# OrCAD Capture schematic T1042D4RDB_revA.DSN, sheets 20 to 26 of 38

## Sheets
20 20 EC2 PHY: size B
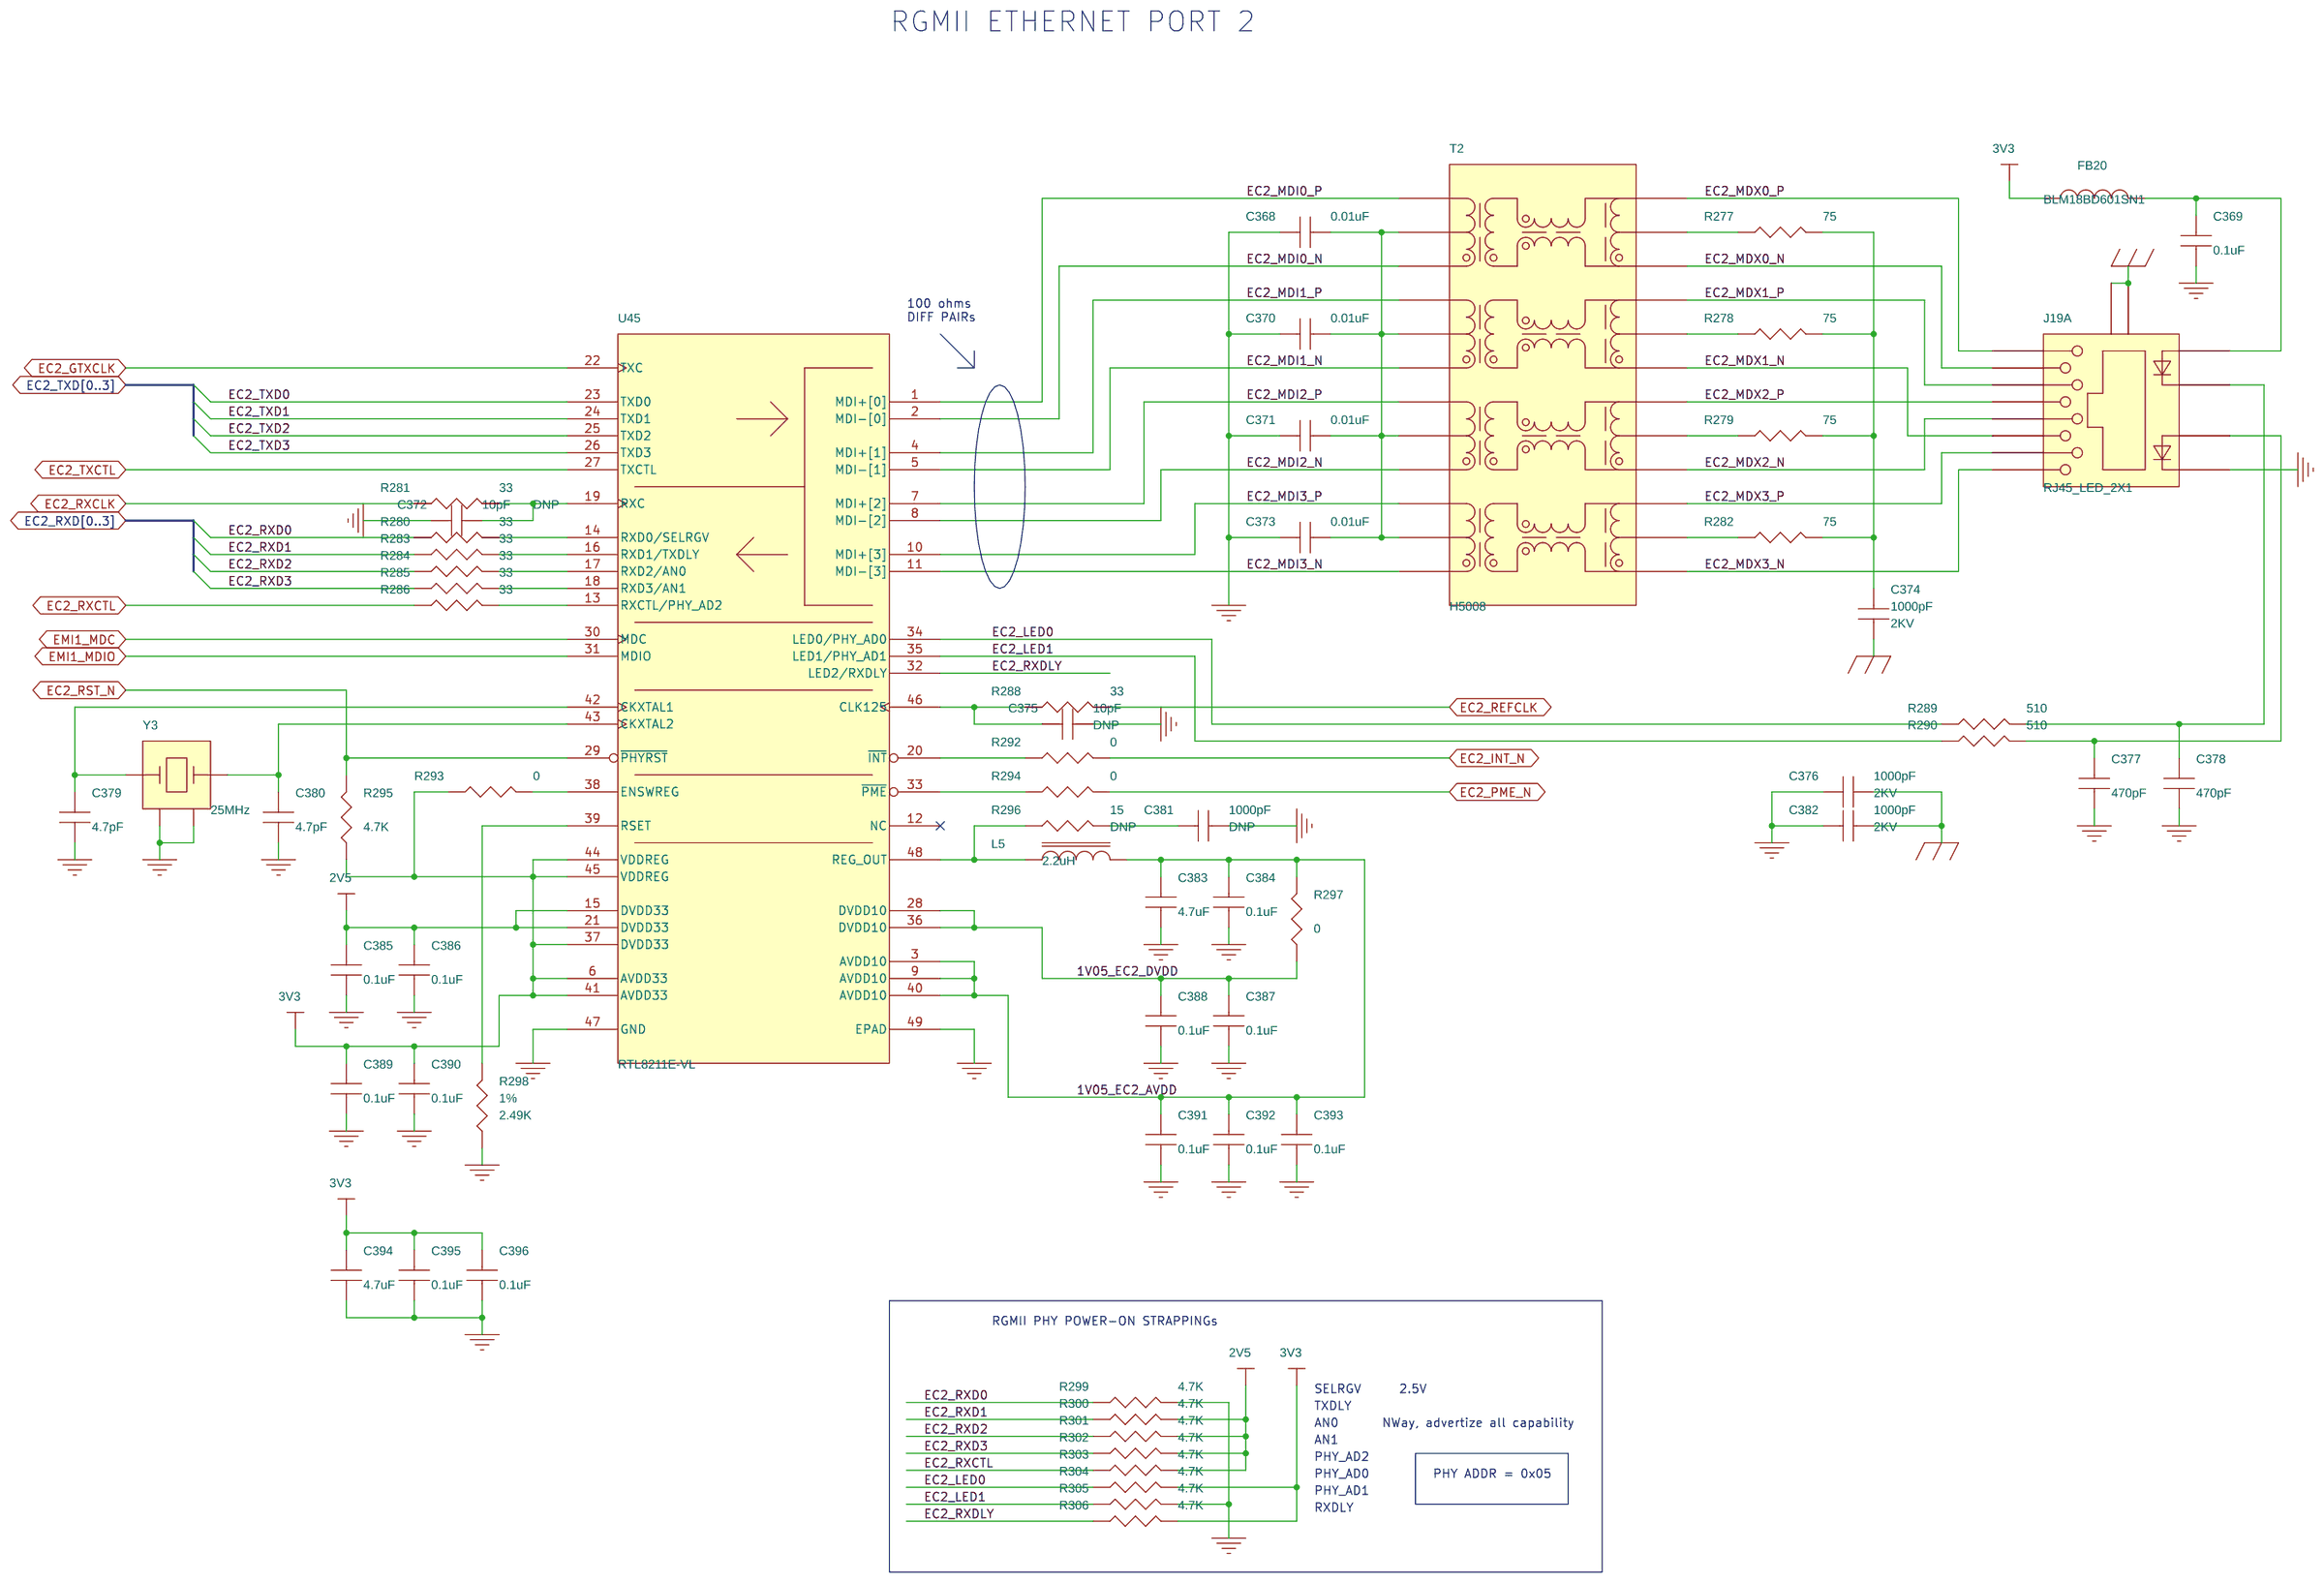
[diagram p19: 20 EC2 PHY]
21 21 SG PHY: size B
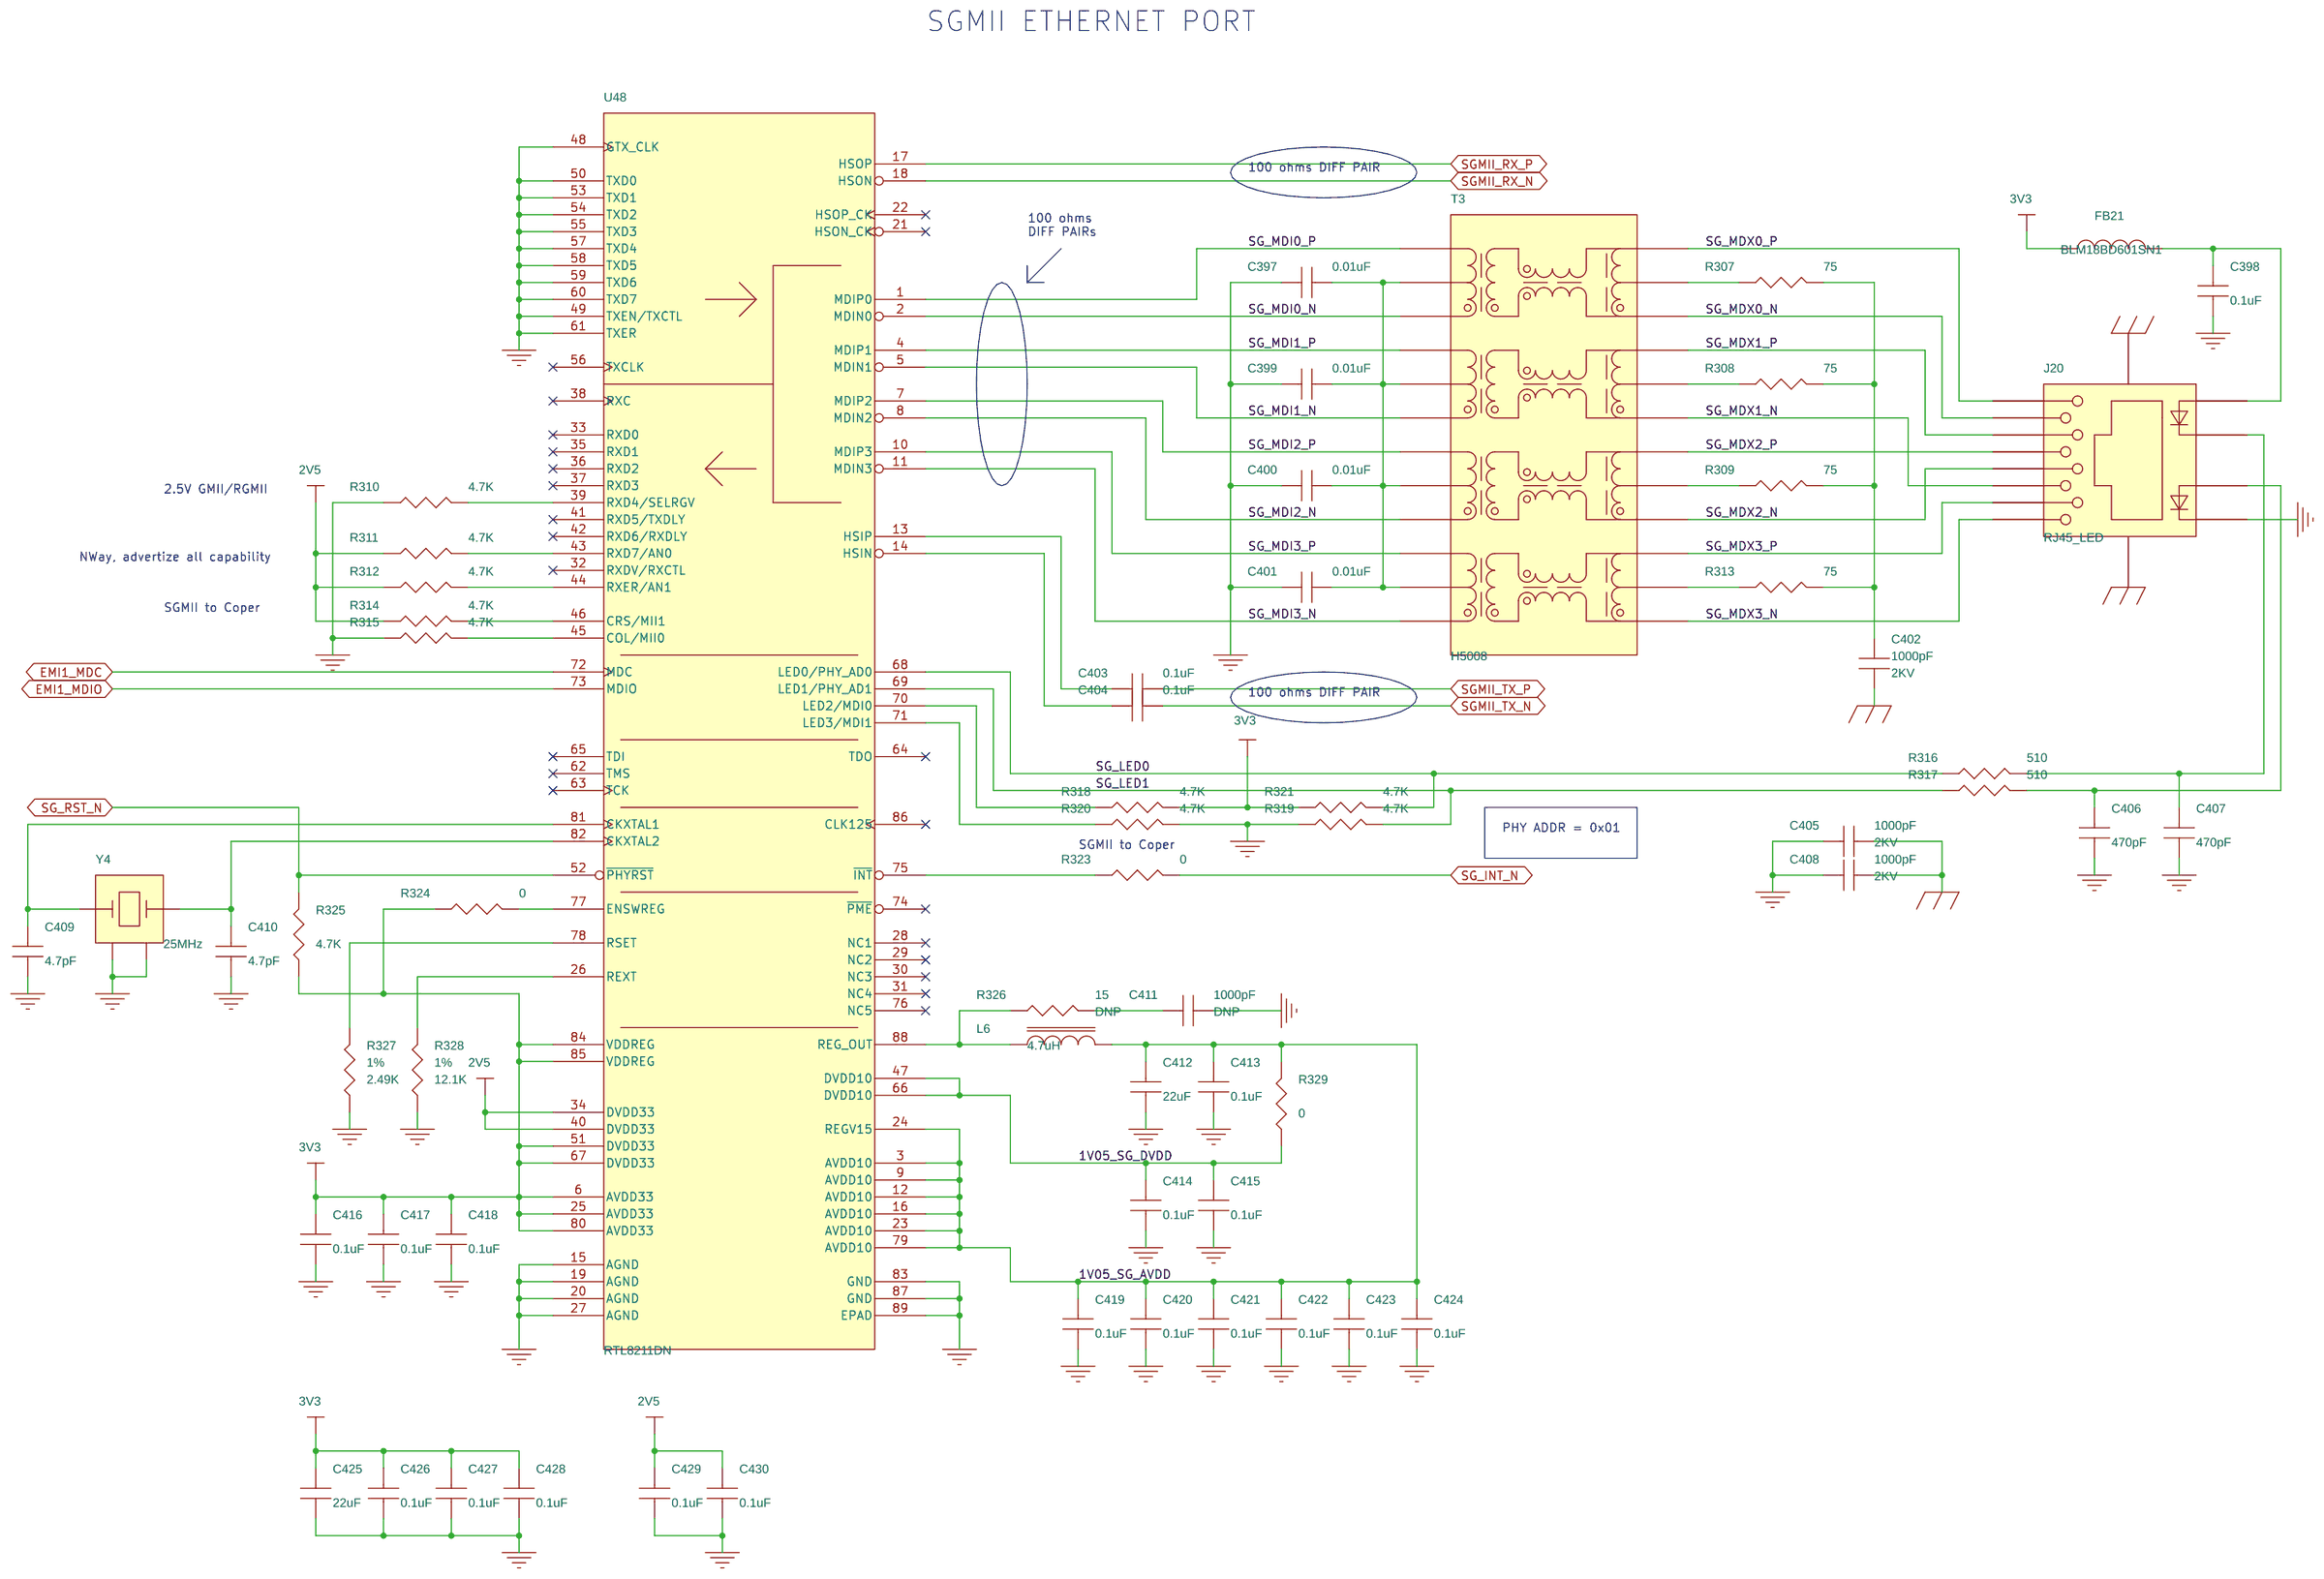
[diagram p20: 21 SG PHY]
22 22 SG PHY1: size B
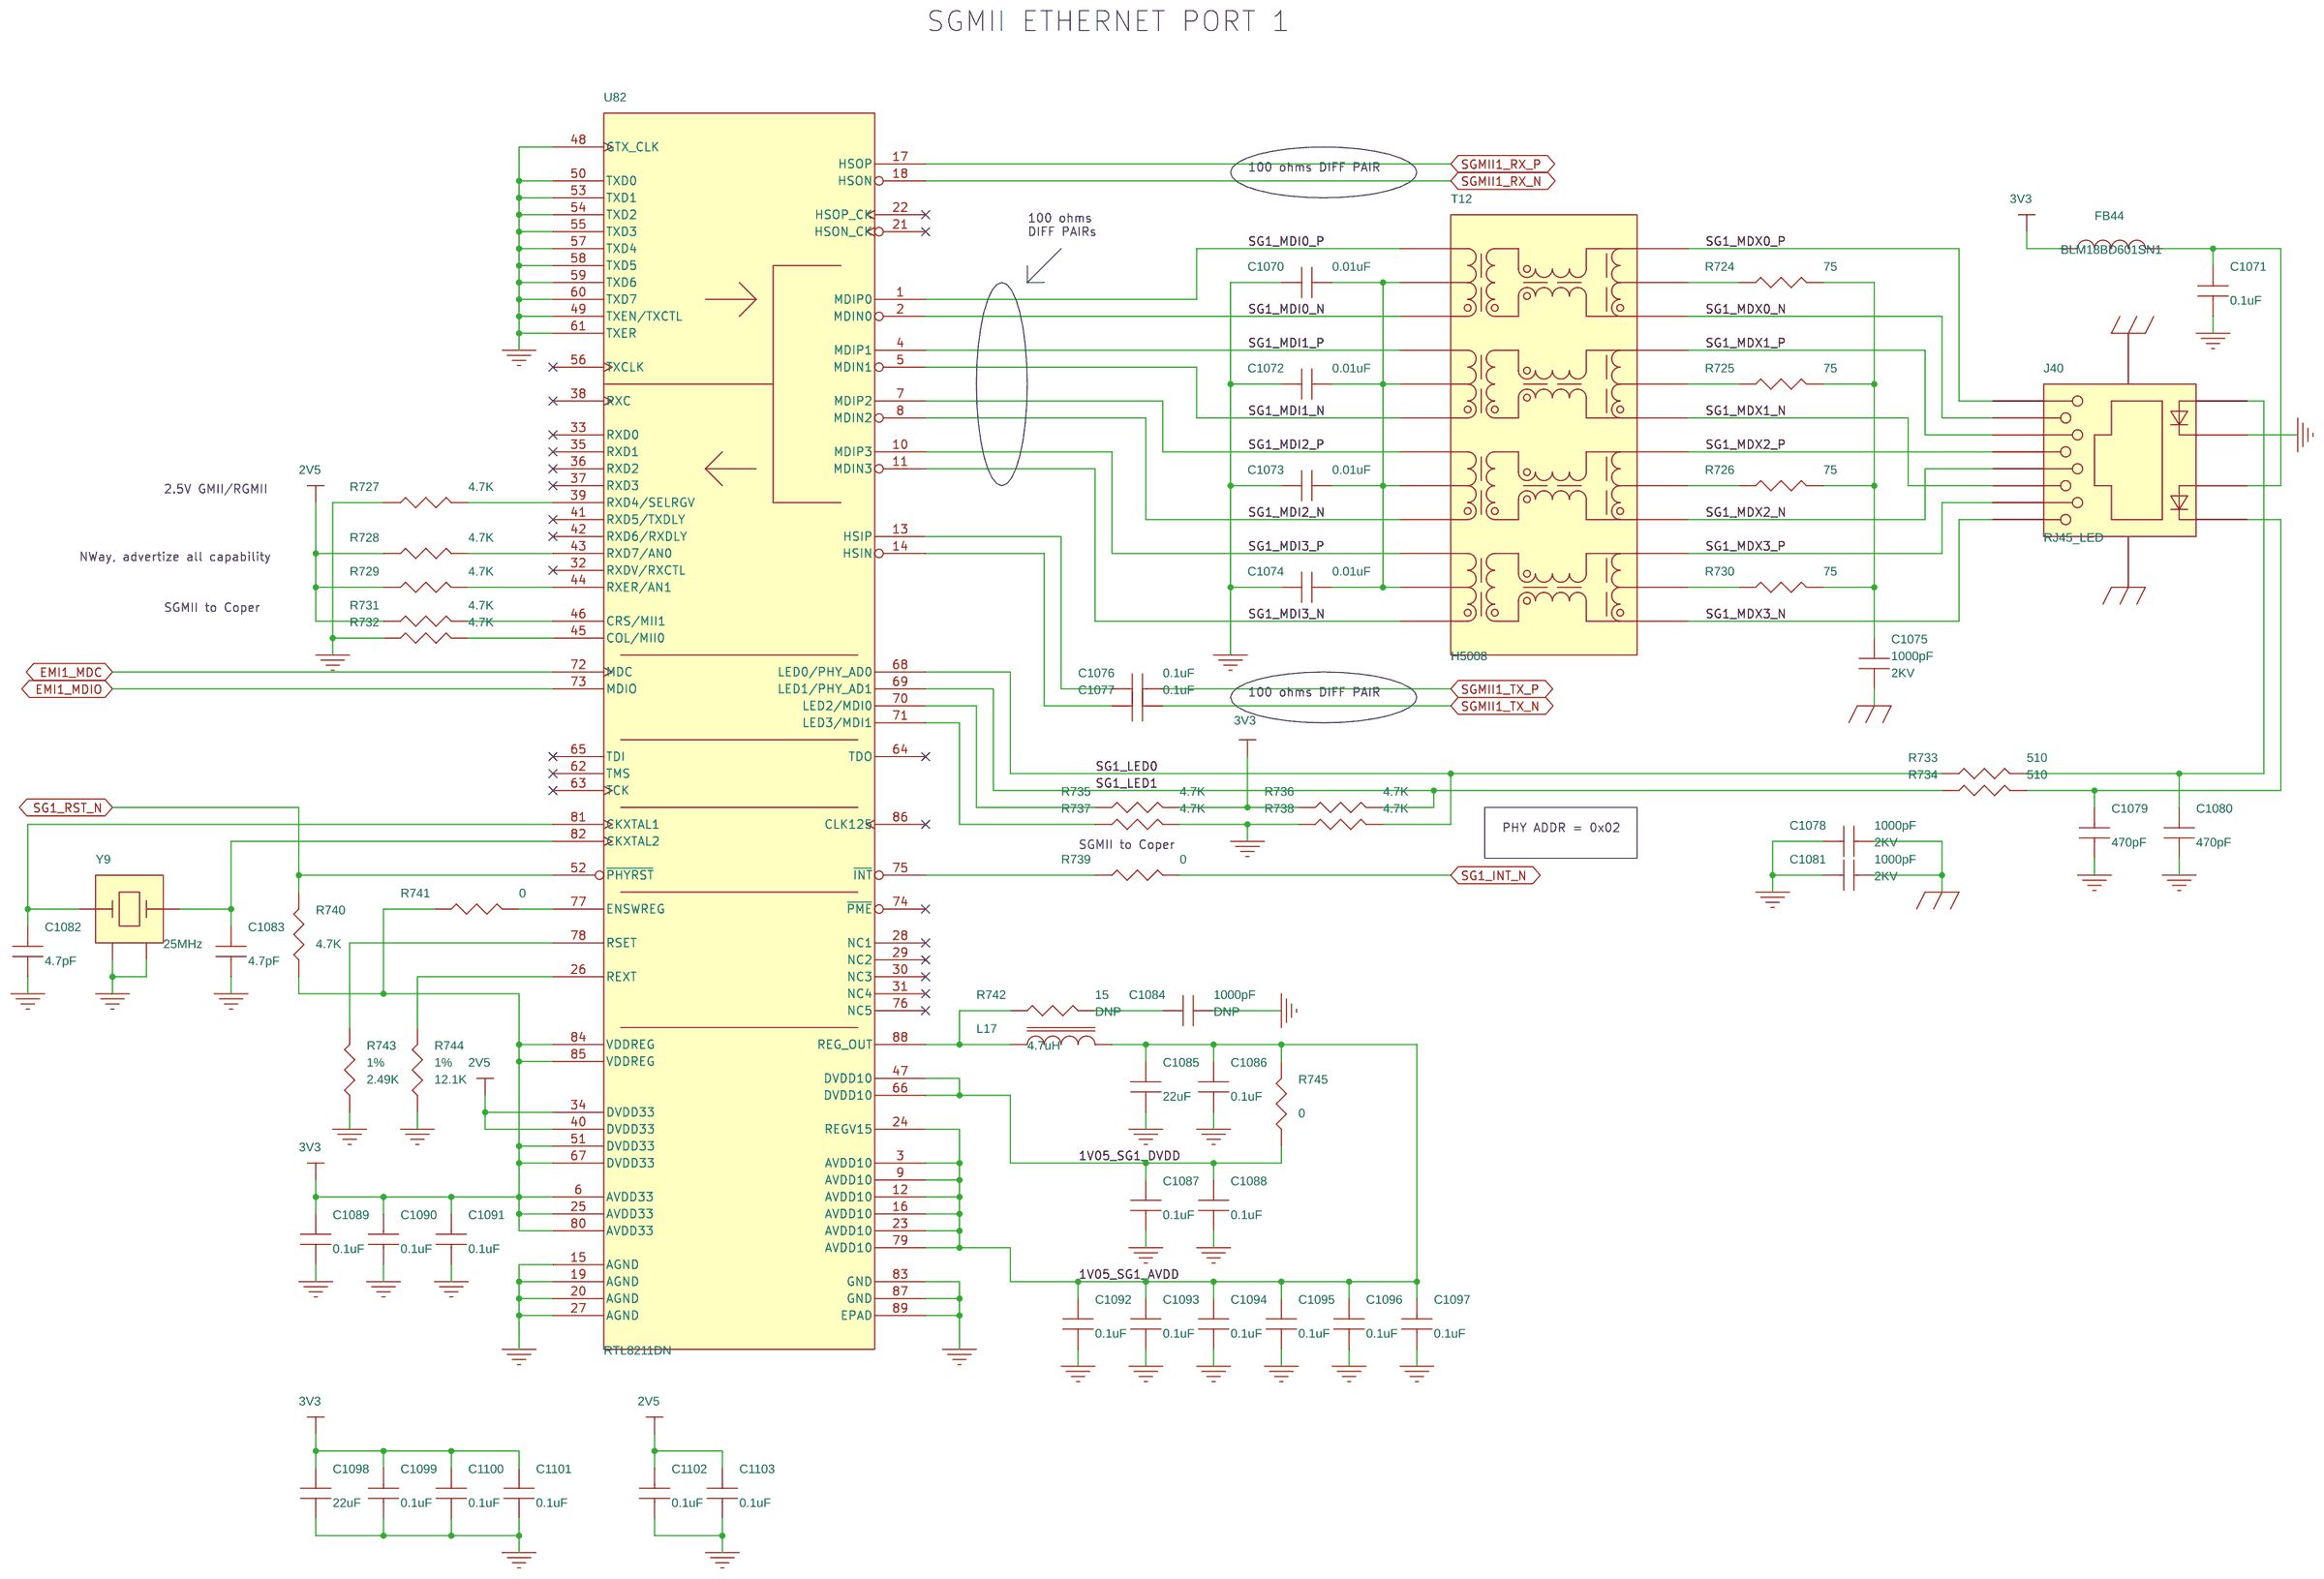
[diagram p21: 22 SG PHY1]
23 23 SG PHY2: size B
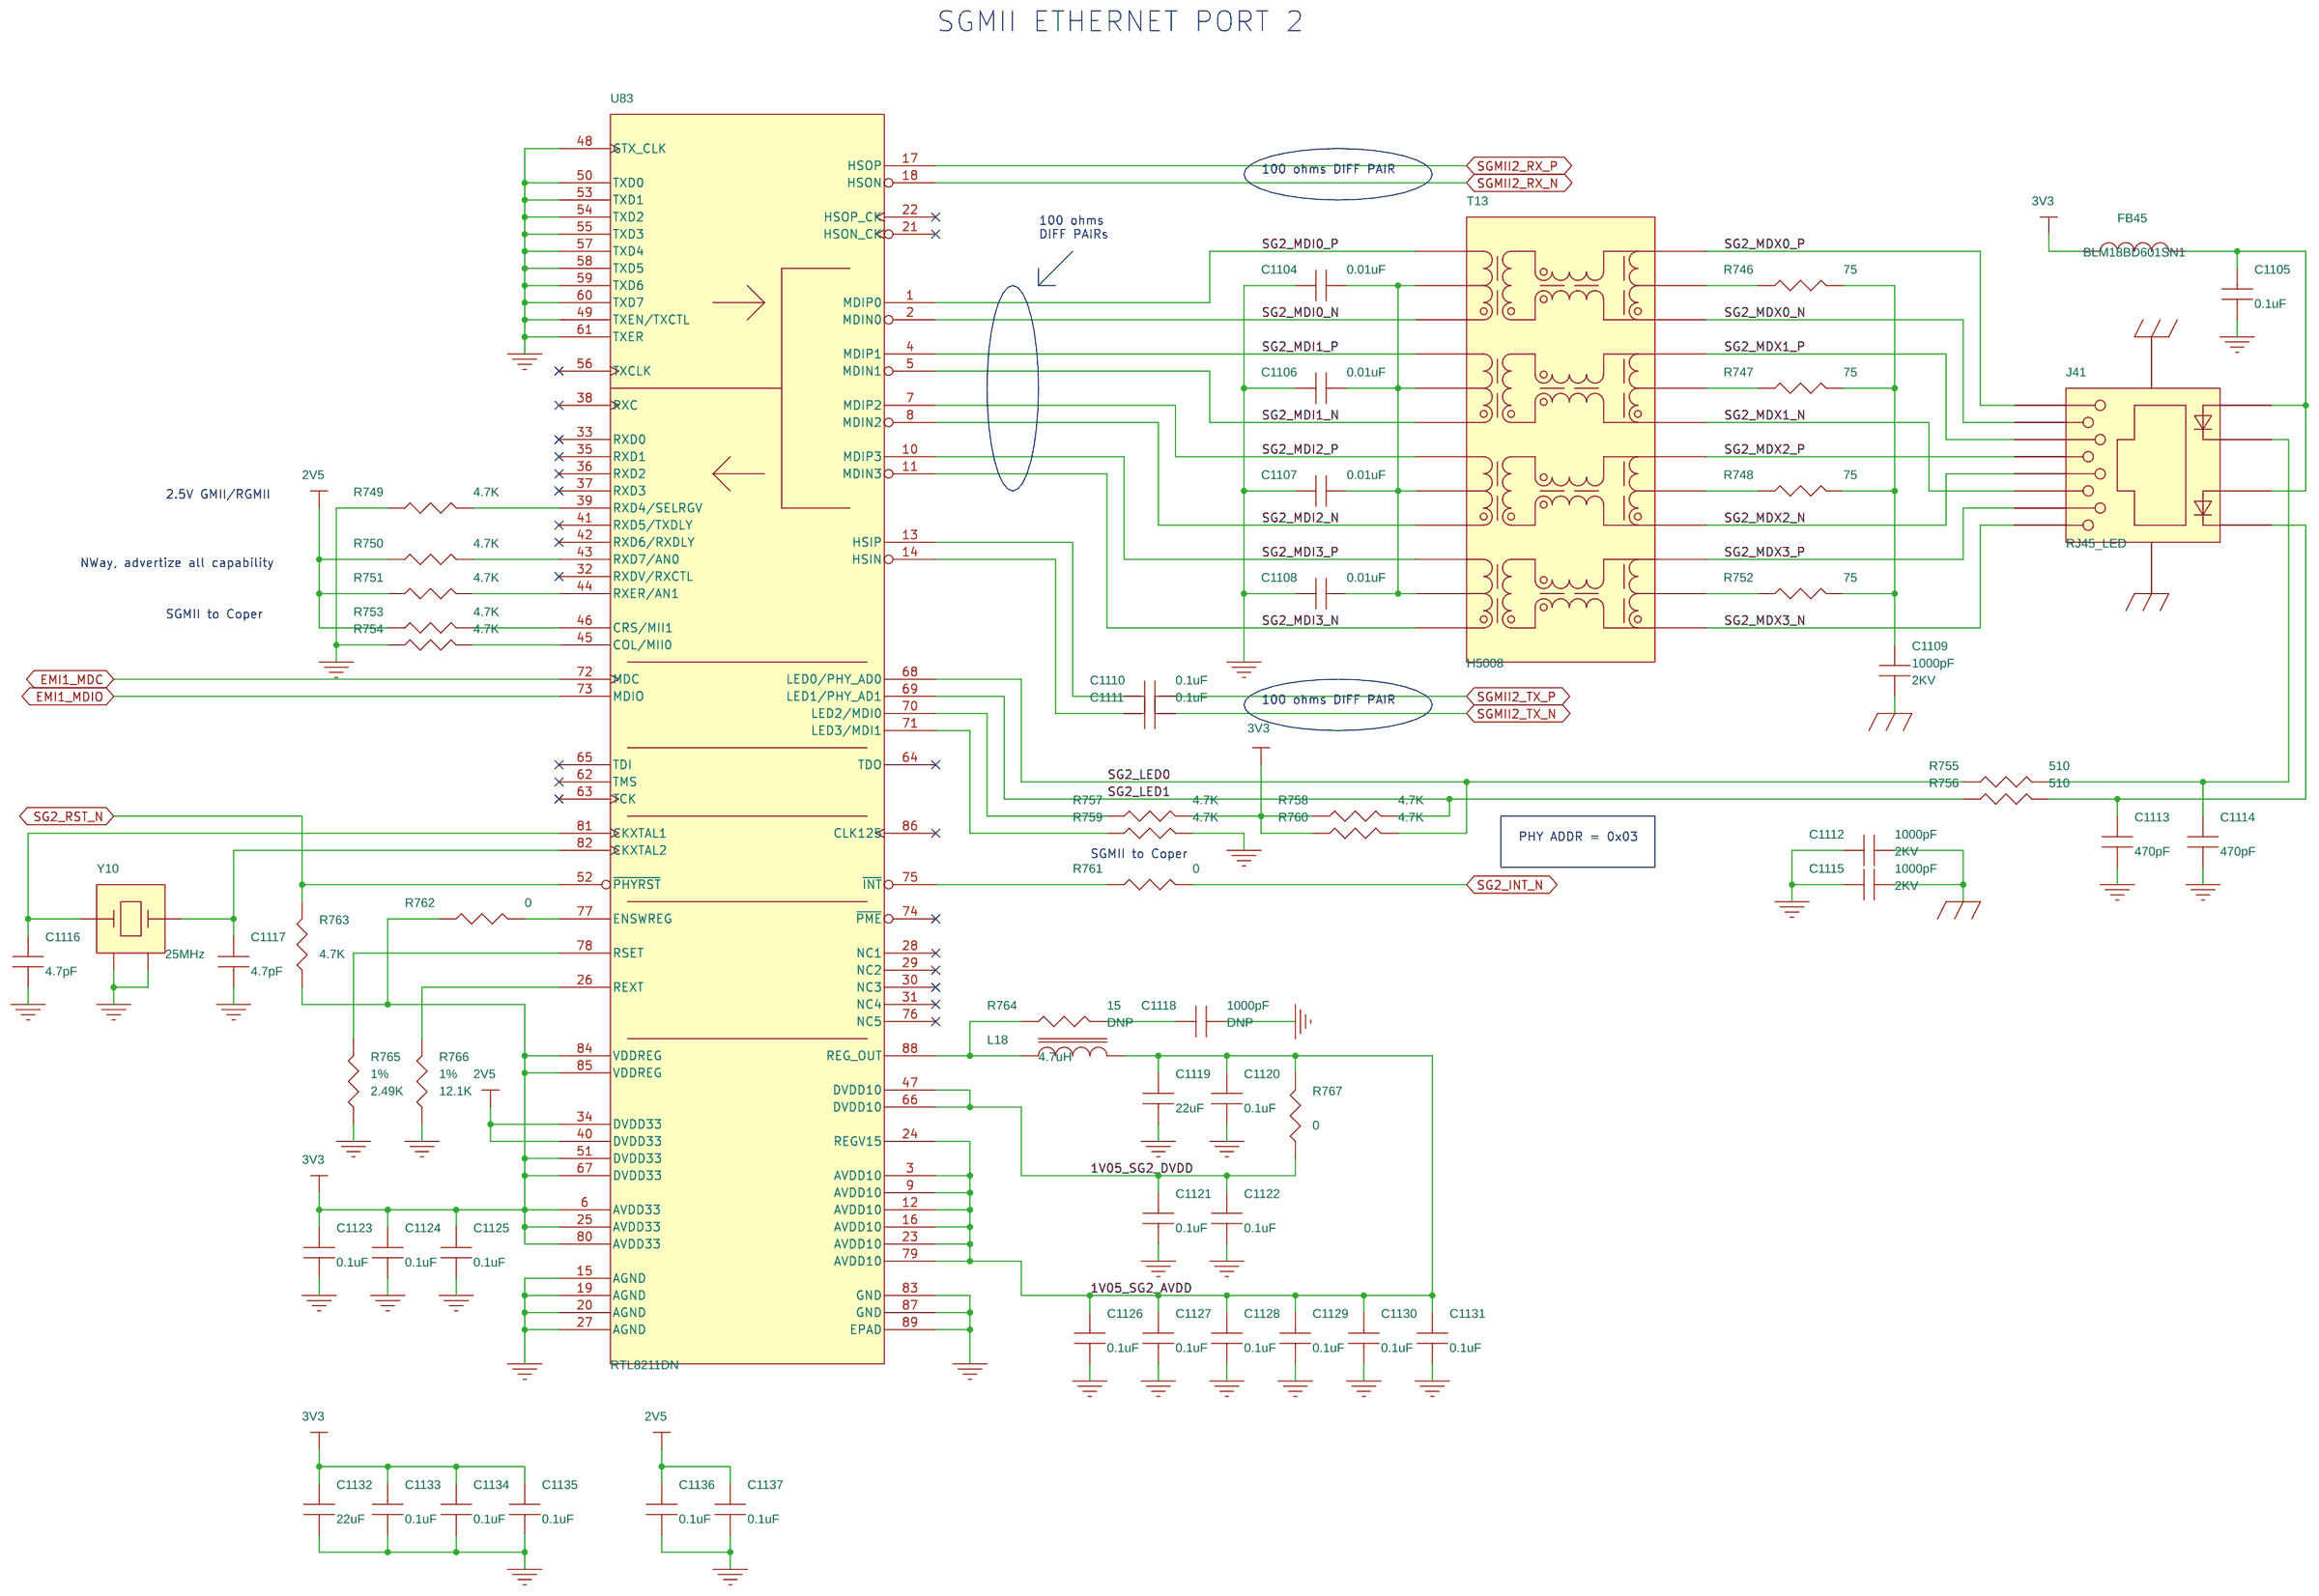
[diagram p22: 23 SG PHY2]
24 24 QSG PHY1: size B
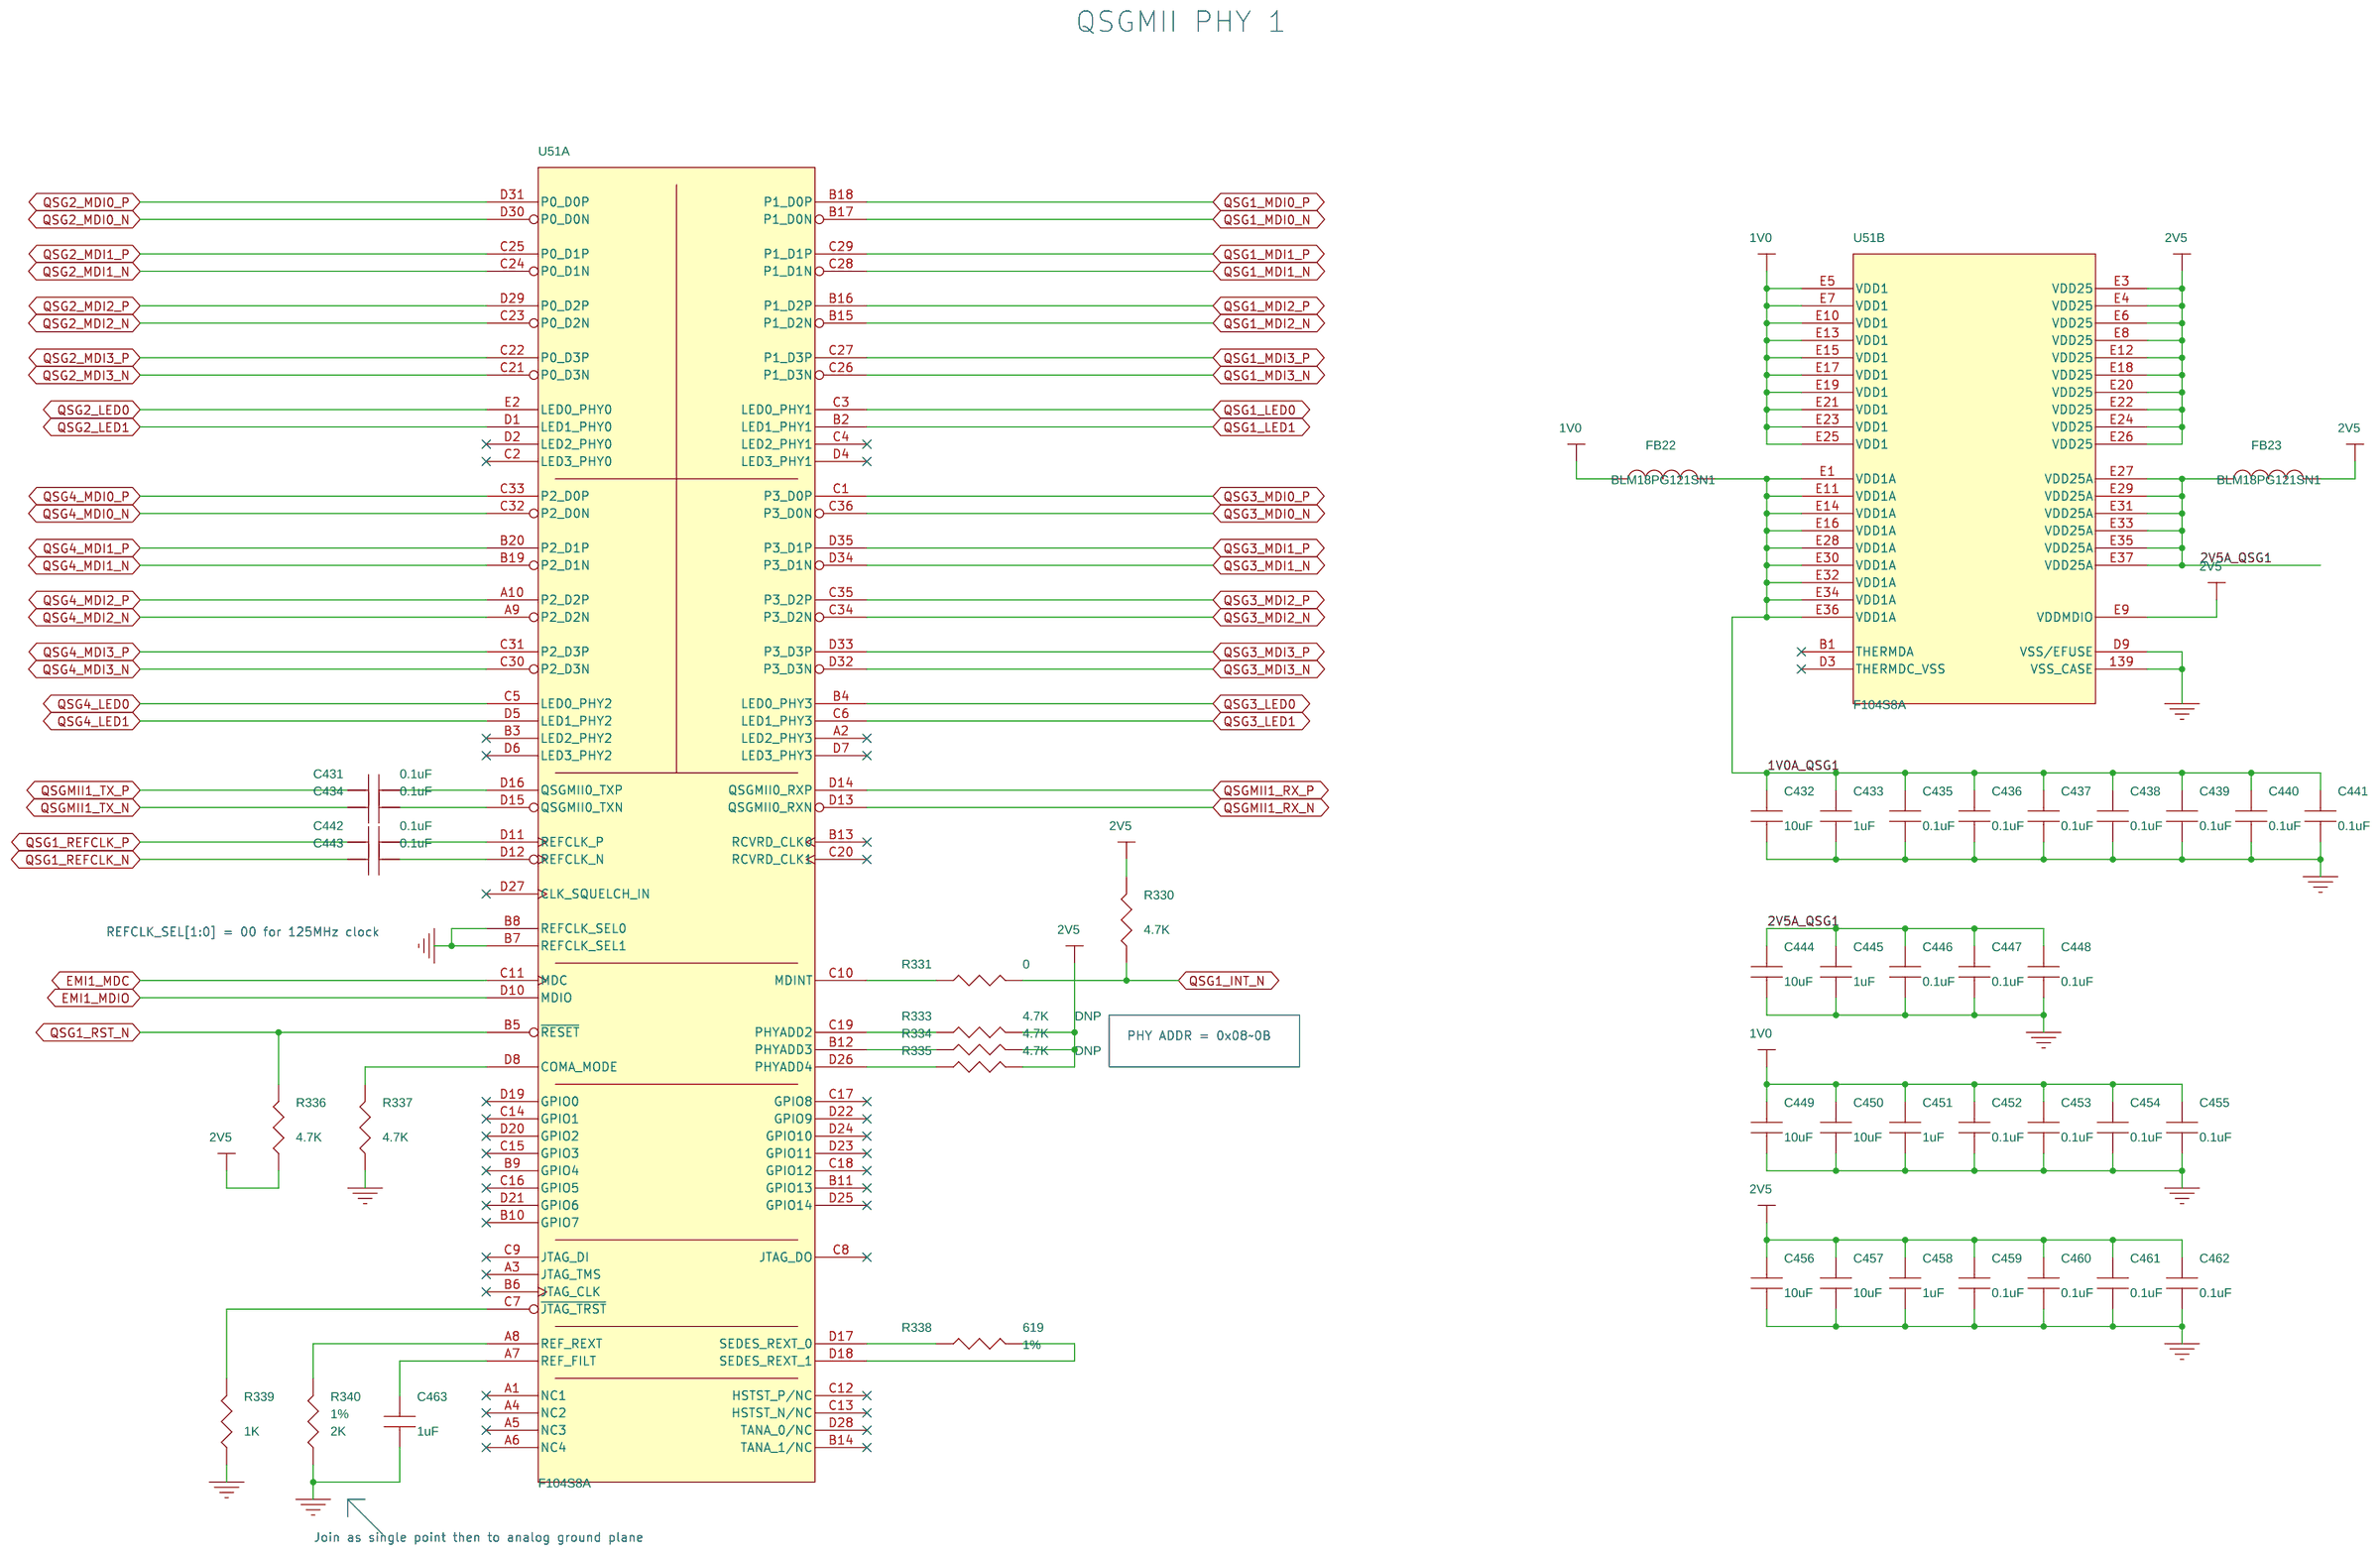
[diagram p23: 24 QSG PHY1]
25 25 QSG PHY2: size B
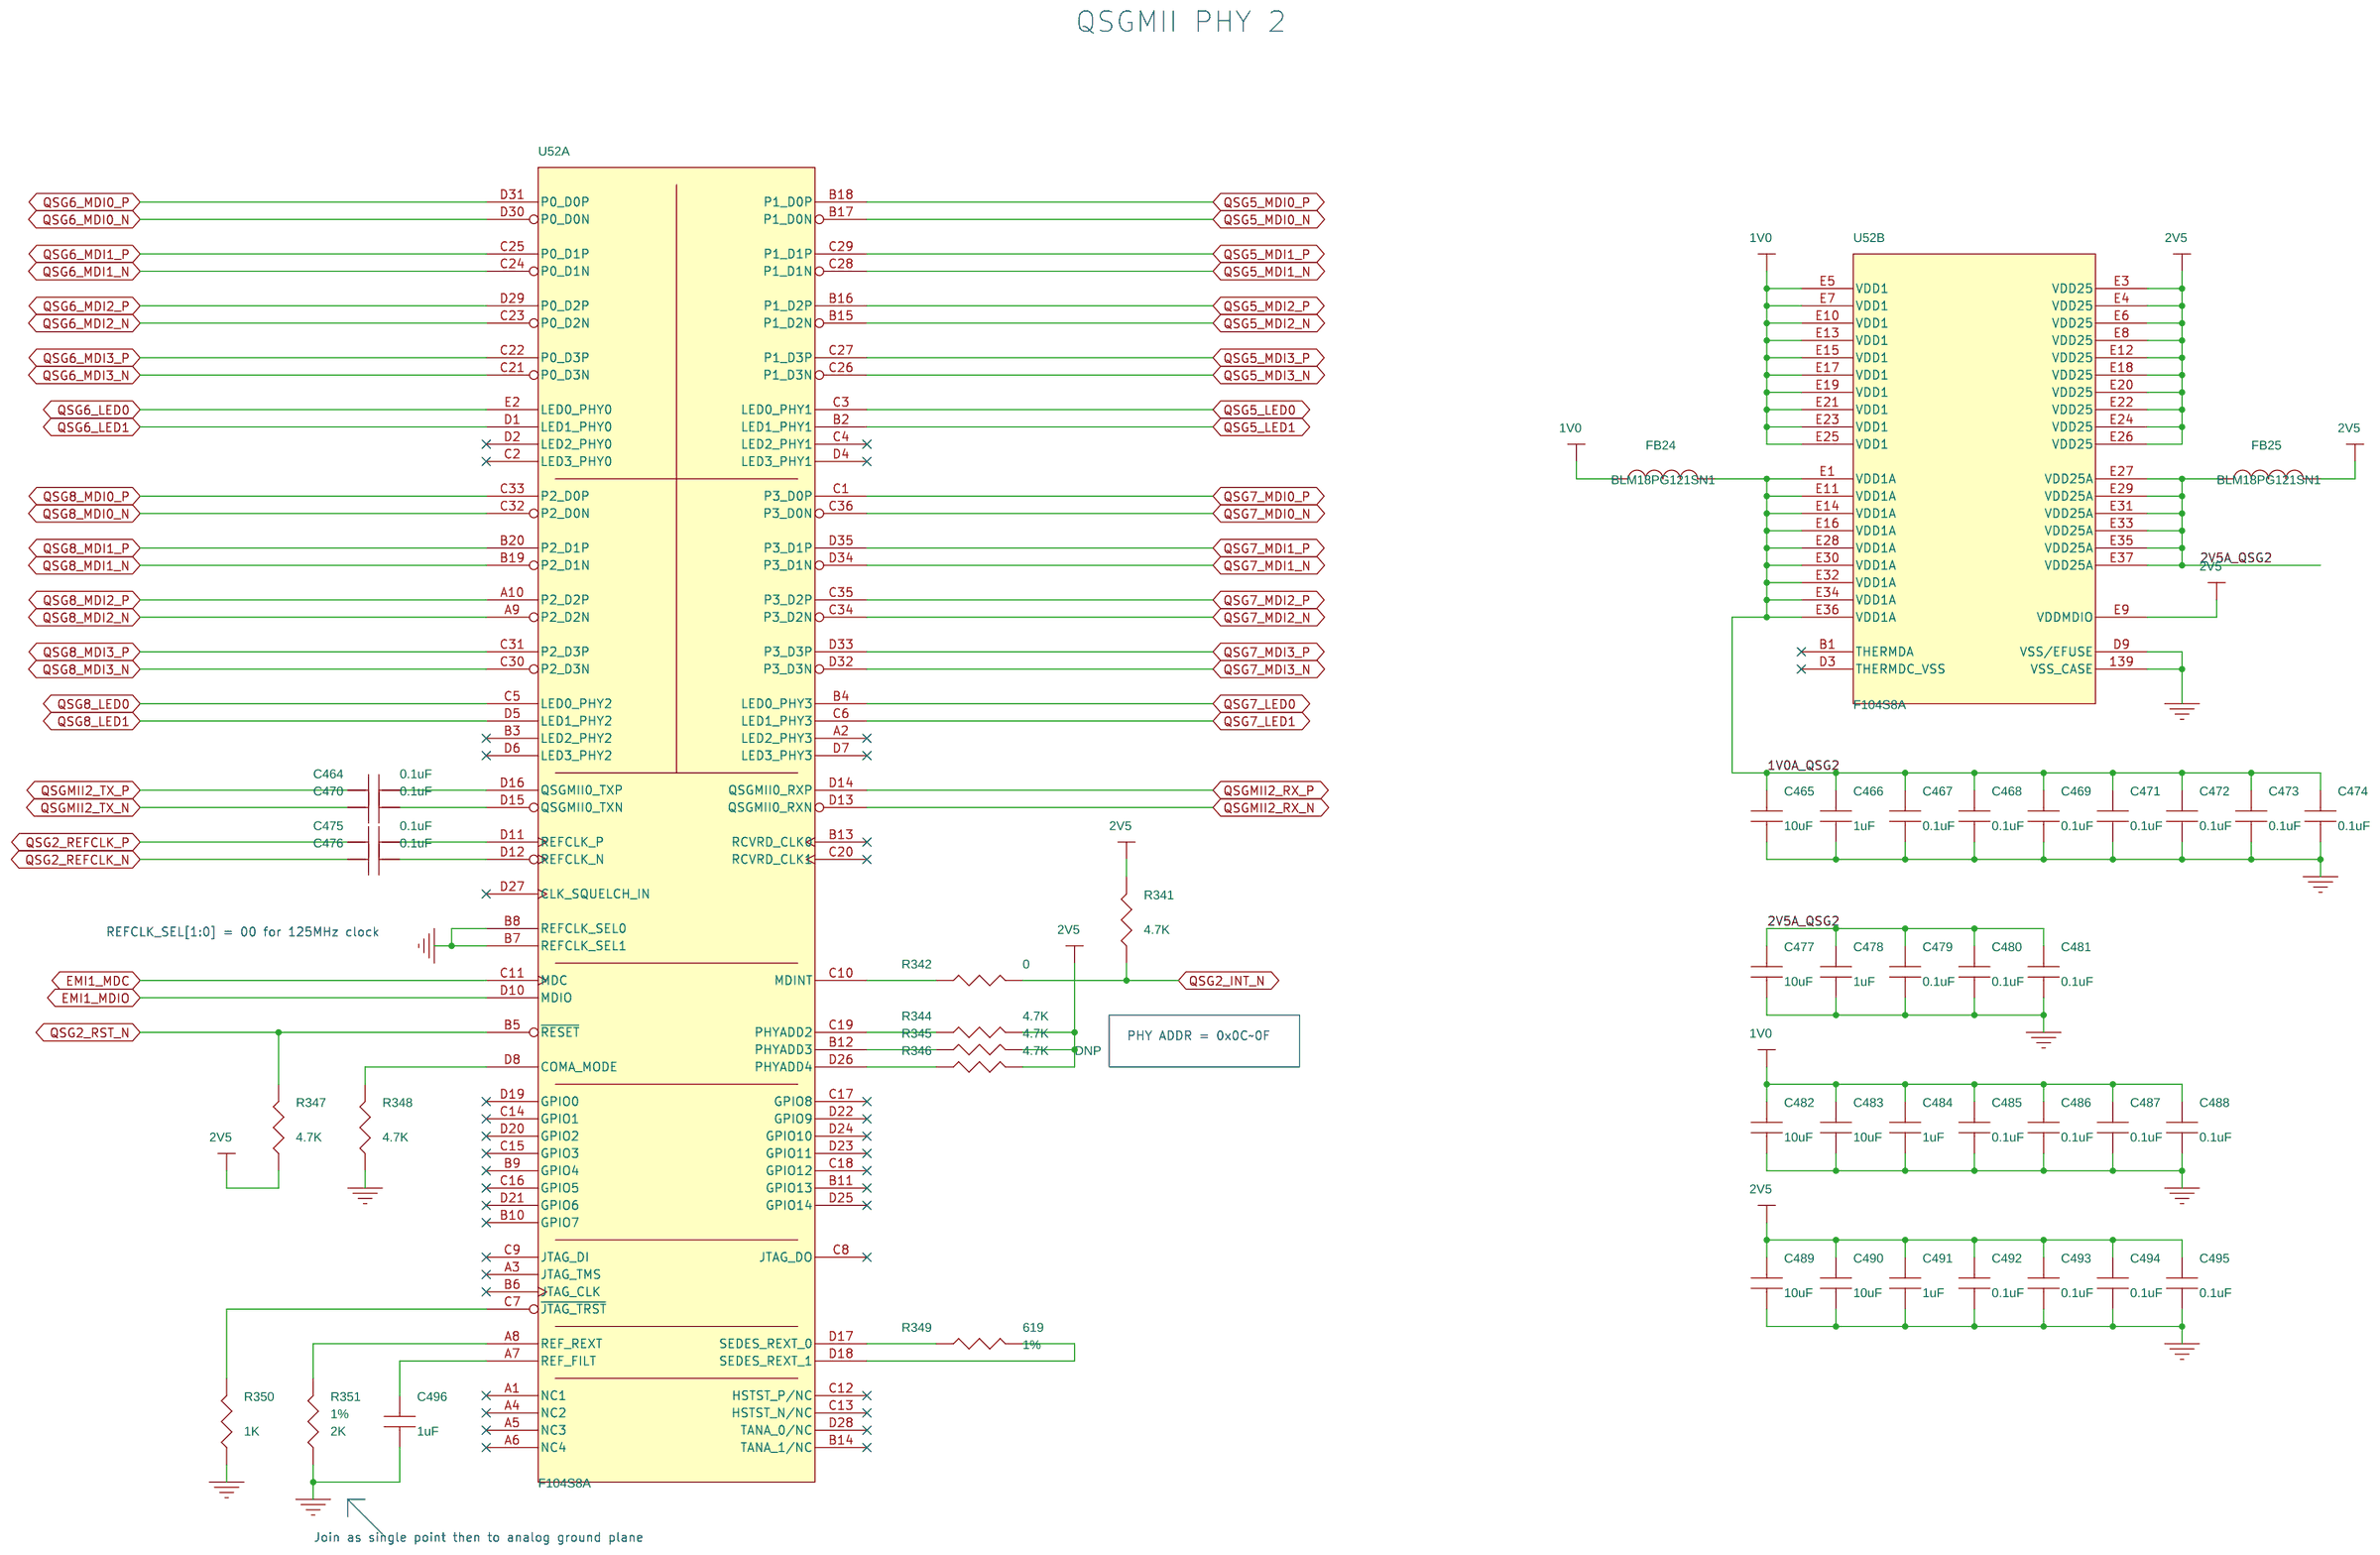
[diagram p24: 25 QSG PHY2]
26 26 QSG RJ45: size B
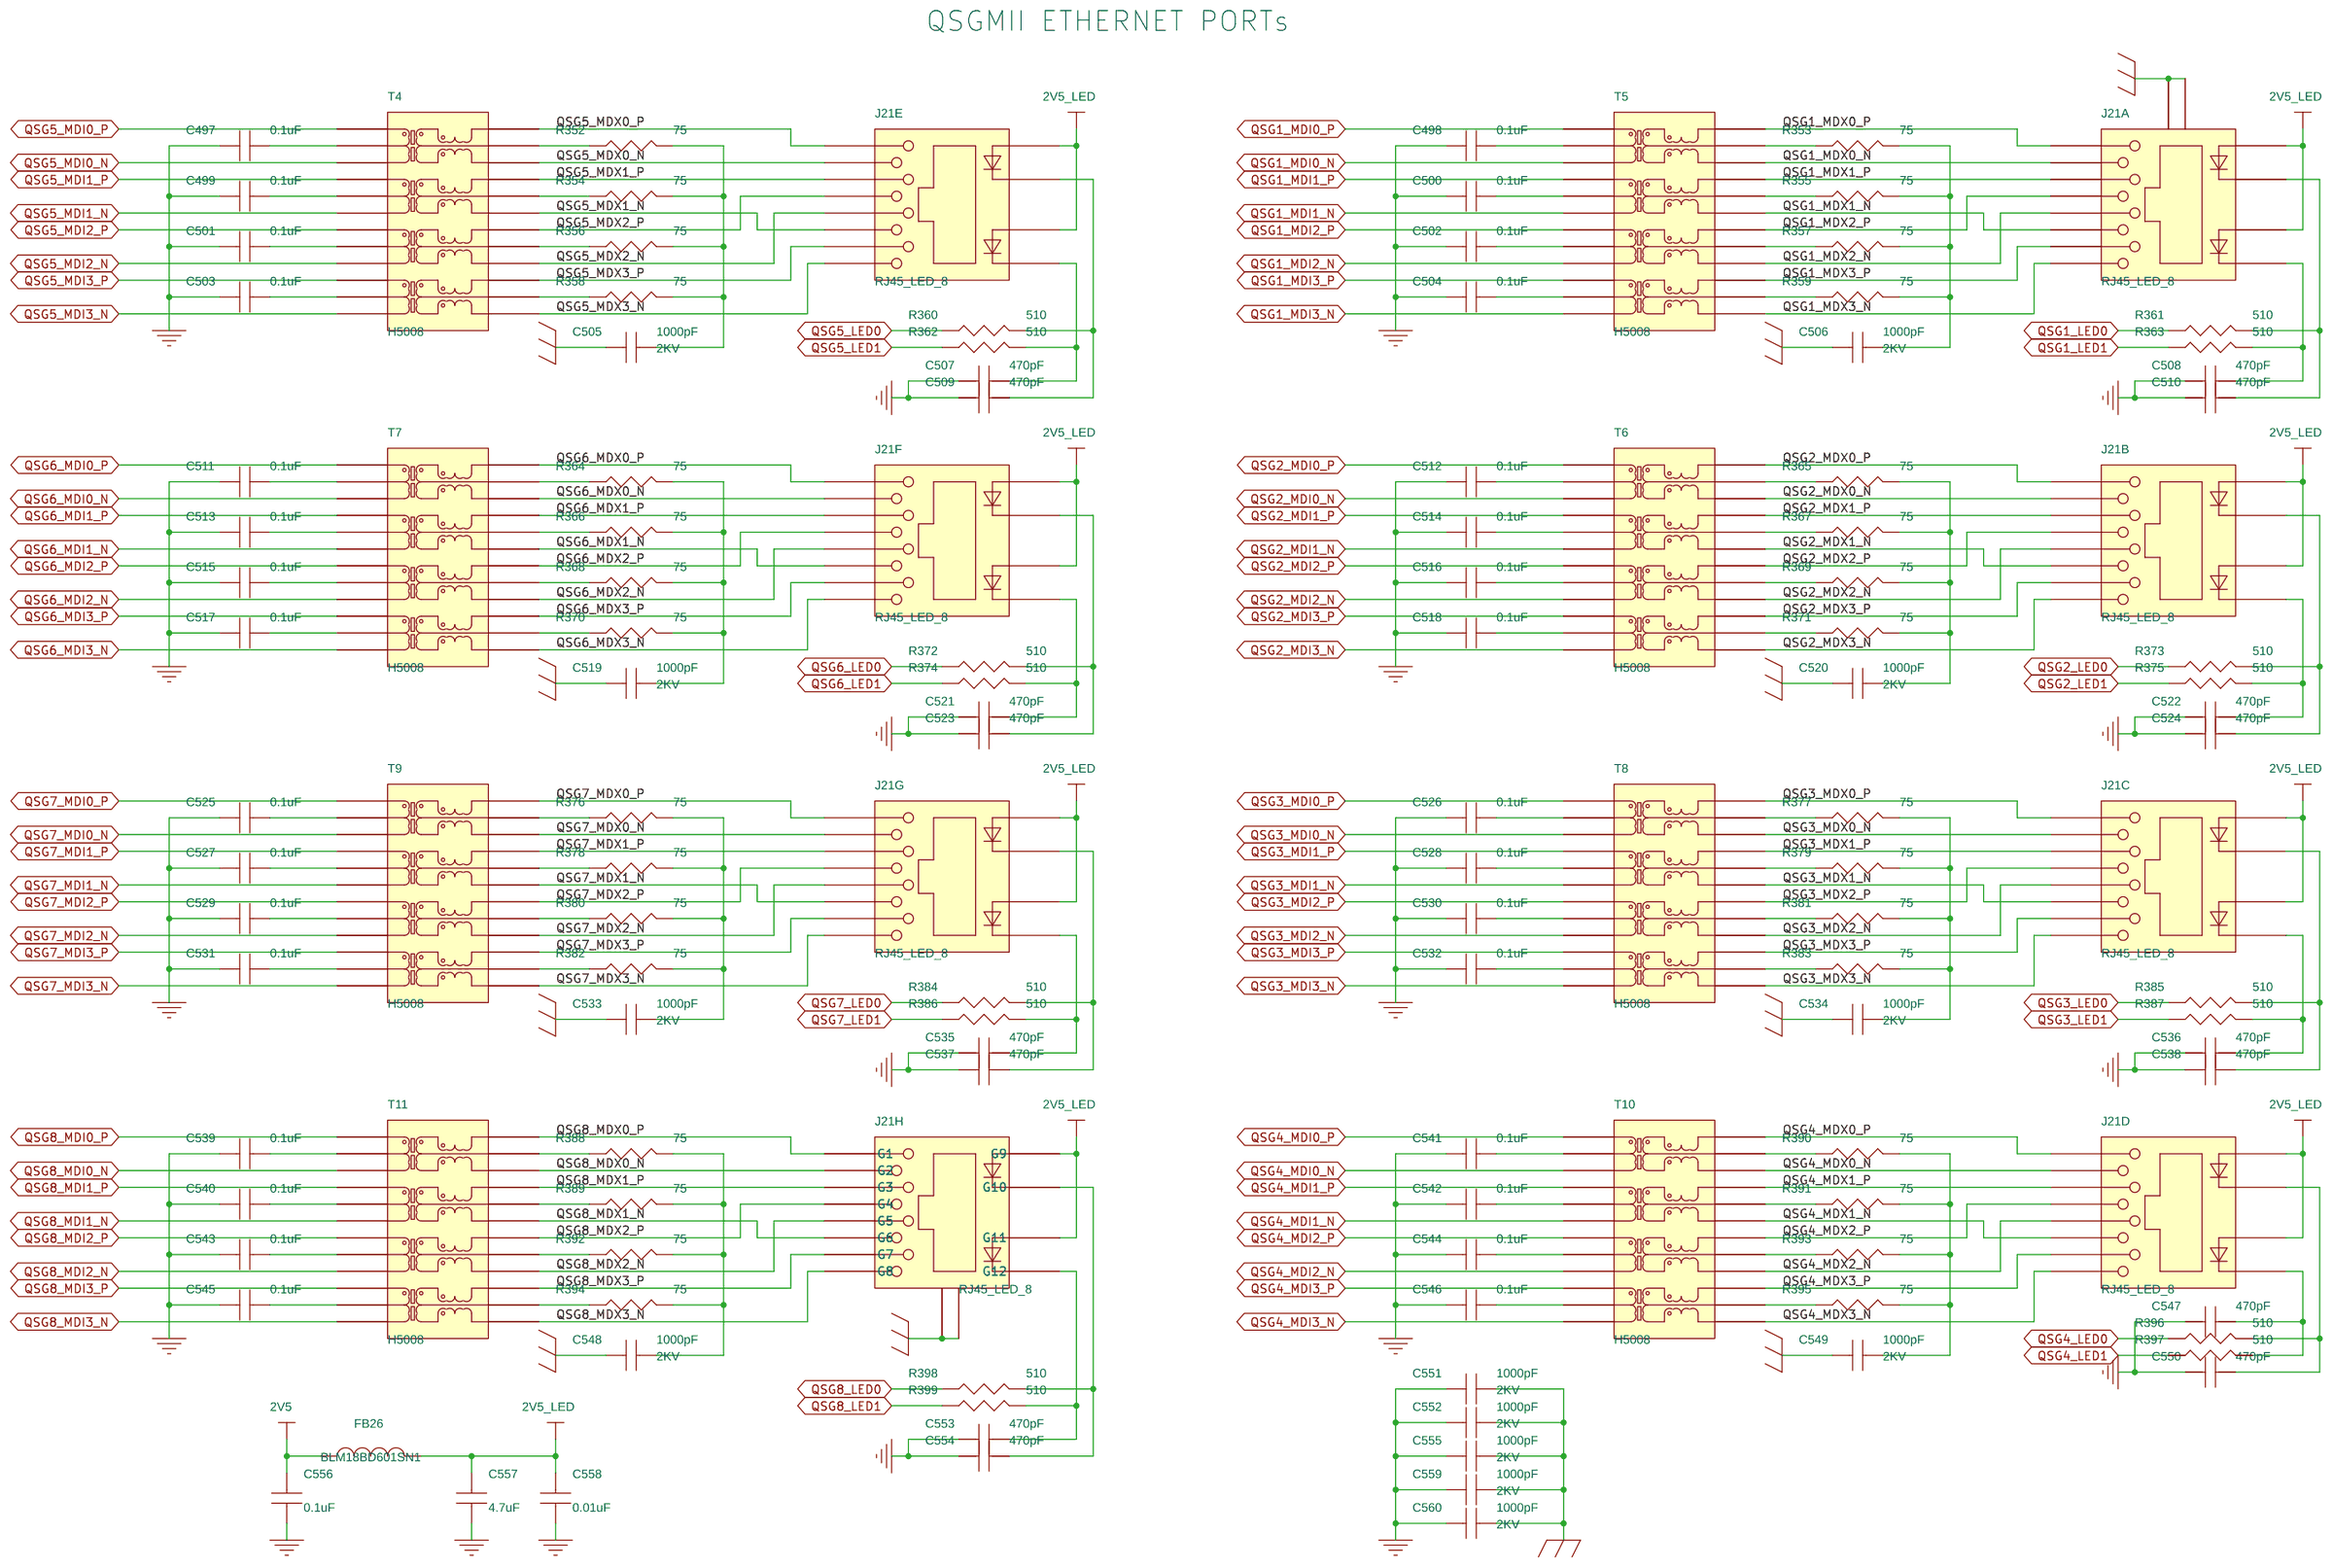
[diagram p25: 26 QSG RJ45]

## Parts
sheet 20 EC2 PHY
C368  0.01uF  [0402]
C369  0.1uF  [0402]
C370  0.01uF  [0402]
C371  0.01uF  [0402]
C372  10pF  [0402]
C373  0.01uF  [0402]
C374  1000pF  [1206]
C375  10pF  [0402]
C376  1000pF  [1206]
C377  470pF  [0402]
C378  470pF  [0402]
C379  4.7pF  [0402]
C380  4.7pF  [0402]
C381  1000pF  [0402]
C382  1000pF  [1206]
C383  4.7uF  [0603]
C384  0.1uF  [0402]
C385  0.1uF  [0402]
C386  0.1uF  [0402]
C387  0.1uF  [0402]
C388  0.1uF  [0402]
C389  0.1uF  [0402]
C390  0.1uF  [0402]
C391  0.1uF  [0402]
C392  0.1uF  [0402]
C393  0.1uF  [0402]
C394  4.7uF  [0603]
C395  0.1uF  [0402]
C396  0.1uF  [0402]
FB20  BLM18BD601SN1  [0603]
J19  RJ45_LED_2X1  [con_rj45_2x1_led]  (sections A,B)
L5  2.2uH  [ind_swpa2520]
R277  75  [0603]
R278  75  [0603]
R279  75  [0603]
R280  33  [0402]
R281  33  [0402]
R282  75  [0603]
R283  33  [0402]
R284  33  [0402]
R285  33  [0402]
R286  33  [0402]
R288  33  [0402]
R289  510  [0402]
R290  510  [0402]
R292  0  [0402]
R293  0  [0402]
R294  0  [0402]
R295  4.7K  [0402]
R296  15  [0402]
R297  0  [0402]
R298  2.49K  [0402]
R299  4.7K  [0402]
R300  4.7K  [0402]
R301  4.7K  [0402]
R302  4.7K  [0402]
R303  4.7K  [0402]
R304  4.7K  [0402]
R305  4.7K  [0402]
R306  4.7K  [0402]
T2  H5008  [mag_h5008]
U45  RTL8211E-VL  [qfn_p040_d040_b600_48_e440]
Y3  25MHz  [cry_32x25_4]
sheet 21 SG PHY
C397  0.01uF  [0402]
C398  0.1uF  [0402]
C399  0.01uF  [0402]
C400  0.01uF  [0402]
C401  0.01uF  [0402]
C402  1000pF  [1206]
C403  0.1uF  [0402]
C404  0.1uF  [0402]
C405  1000pF  [1206]
C406  470pF  [0402]
C407  470pF  [0402]
C408  1000pF  [1206]
C409  4.7pF  [0402]
C410  4.7pF  [0402]
C411  1000pF  [0402]
C412  22uF  [0805]
C413  0.1uF  [0402]
C414  0.1uF  [0402]
C415  0.1uF  [0402]
C416  0.1uF  [0402]
C417  0.1uF  [0402]
C418  0.1uF  [0402]
C419  0.1uF  [0402]
C420  0.1uF  [0402]
C421  0.1uF  [0402]
C422  0.1uF  [0402]
C423  0.1uF  [0402]
C424  0.1uF  [0402]
C425  22uF  [0805]
C426  0.1uF  [0402]
C427  0.1uF  [0402]
C428  0.1uF  [0402]
C429  0.1uF  [0402]
C430  0.1uF  [0402]
FB21  BLM18BD601SN1  [0603]
J20  RJ45_LED  [con_rj45_up_1x1_led]
L6  4.7uH  [ind_swpa2520]
R307  75  [0603]
R308  75  [0603]
R309  75  [0603]
R310  4.7K  [0402]
R311  4.7K  [0402]
R312  4.7K  [0402]
R313  75  [0603]
R314  4.7K  [0402]
R315  4.7K  [0402]
R316  510  [0402]
R317  510  [0402]
R318  4.7K  [0402]
R319  4.7K  [0402]
R320  4.7K  [0402]
R321  4.7K  [0402]
R323  0  [0402]
R324  0  [0402]
R325  4.7K  [0402]
R326  15  [0402]
R327  2.49K  [0402]
R328  12.1K  [0402]
R329  0  [0402]
T3  H5008  [mag_h5008]
U48  RTL8211DN  [qfn_p040_d040_b1000_88_e600]
Y4  25MHz  [cry_32x25_4]
sheet 22 SG PHY1
C1070  0.01uF  [0402]
C1071  0.1uF  [0402]
C1072  0.01uF  [0402]
C1073  0.01uF  [0402]
C1074  0.01uF  [0402]
C1075  1000pF  [1206]
C1076  0.1uF  [0402]
C1077  0.1uF  [0402]
C1078  1000pF  [1206]
C1079  470pF  [0402]
C1080  470pF  [0402]
C1081  1000pF  [1206]
C1082  4.7pF  [0402]
C1083  4.7pF  [0402]
C1084  1000pF  [0402]
C1085  22uF  [0805]
C1086  0.1uF  [0402]
C1087  0.1uF  [0402]
C1088  0.1uF  [0402]
C1089  0.1uF  [0402]
C1090  0.1uF  [0402]
C1091  0.1uF  [0402]
C1092  0.1uF  [0402]
C1093  0.1uF  [0402]
C1094  0.1uF  [0402]
C1095  0.1uF  [0402]
C1096  0.1uF  [0402]
C1097  0.1uF  [0402]
C1098  22uF  [0805]
C1099  0.1uF  [0402]
C1100  0.1uF  [0402]
C1101  0.1uF  [0402]
C1102  0.1uF  [0402]
C1103  0.1uF  [0402]
FB44  BLM18BD601SN1  [0603]
J40  RJ45_LED  [con_rj45_up_1x1_led]
L17  4.7uH  [ind_swpa2520]
R724  75  [0603]
R725  75  [0603]
R726  75  [0603]
R727  4.7K  [0402]
R728  4.7K  [0402]
R729  4.7K  [0402]
R730  75  [0603]
R731  4.7K  [0402]
R732  4.7K  [0402]
R733  510  [0402]
R734  510  [0402]
R735  4.7K  [0402]
R736  4.7K  [0402]
R737  4.7K  [0402]
R738  4.7K  [0402]
R739  0  [0402]
R740  4.7K  [0402]
R741  0  [0402]
R742  15  [0402]
R743  2.49K  [0402]
R744  12.1K  [0402]
R745  0  [0402]
T12  H5008  [mag_h5008]
U82  RTL8211DN  [qfn_p040_d040_b1000_88_e600]
Y9  25MHz  [cry_32x25_4]
sheet 23 SG PHY2
C1104  0.01uF  [0402]
C1105  0.1uF  [0402]
C1106  0.01uF  [0402]
C1107  0.01uF  [0402]
C1108  0.01uF  [0402]
C1109  1000pF  [1206]
C1110  0.1uF  [0402]
C1111  0.1uF  [0402]
C1112  1000pF  [1206]
C1113  470pF  [0402]
C1114  470pF  [0402]
C1115  1000pF  [1206]
C1116  4.7pF  [0402]
C1117  4.7pF  [0402]
C1118  1000pF  [0402]
C1119  22uF  [0805]
C1120  0.1uF  [0402]
C1121  0.1uF  [0402]
C1122  0.1uF  [0402]
C1123  0.1uF  [0402]
C1124  0.1uF  [0402]
C1125  0.1uF  [0402]
C1126  0.1uF  [0402]
C1127  0.1uF  [0402]
C1128  0.1uF  [0402]
C1129  0.1uF  [0402]
C1130  0.1uF  [0402]
C1131  0.1uF  [0402]
C1132  22uF  [0805]
C1133  0.1uF  [0402]
C1134  0.1uF  [0402]
C1135  0.1uF  [0402]
C1136  0.1uF  [0402]
C1137  0.1uF  [0402]
FB45  BLM18BD601SN1  [0603]
J41  RJ45_LED  [con_rj45_up_1x1_led]
L18  4.7uH  [ind_swpa2520]
R746  75  [0603]
R747  75  [0603]
R748  75  [0603]
R749  4.7K  [0402]
R750  4.7K  [0402]
R751  4.7K  [0402]
R752  75  [0603]
R753  4.7K  [0402]
R754  4.7K  [0402]
R755  510  [0402]
R756  510  [0402]
R757  4.7K  [0402]
R758  4.7K  [0402]
R759  4.7K  [0402]
R760  4.7K  [0402]
R761  0  [0402]
R762  0  [0402]
R763  4.7K  [0402]
R764  15  [0402]
R765  2.49K  [0402]
R766  12.1K  [0402]
R767  0  [0402]
T13  H5008  [mag_h5008]
U83  RTL8211DN  [qfn_p040_d040_b1000_88_e600]
Y10  25MHz  [cry_32x25_4]
sheet 24 QSG PHY1
C431  0.1uF  [0402]
C432  10uF  [0603]
C433  1uF  [0402]
C434  0.1uF  [0402]
C435  0.1uF  [0402]
C436  0.1uF  [0402]
C437  0.1uF  [0402]
C438  0.1uF  [0402]
C439  0.1uF  [0402]
C440  0.1uF  [0402]
C441  0.1uF  [0402]
C442  0.1uF  [0402]
C443  0.1uF  [0402]
C444  10uF  [0603]
C445  1uF  [0402]
C446  0.1uF  [0402]
C447  0.1uF  [0402]
C448  0.1uF  [0402]
C449  10uF  [0603]
C450  10uF  [0603]
C451  1uF  [0402]
C452  0.1uF  [0402]
C453  0.1uF  [0402]
C454  0.1uF  [0402]
C455  0.1uF  [0402]
C456  10uF  [0603]
C457  10uF  [0603]
C458  1uF  [0402]
C459  0.1uF  [0402]
C460  0.1uF  [0402]
C461  0.1uF  [0402]
C462  0.1uF  [0402]
C463  1uF  [0402]
FB22  BLM18PG121SN1  [0603]
FB23  BLM18PG121SN1  [0603]
R330  4.7K  [0402]
R331  0  [0402]
R333  4.7K  [0402]
R334  4.7K  [0402]
R335  4.7K  [0402]
R336  4.7K  [0402]
R337  4.7K  [0402]
R338  619  [0402]
R339  1K  [0402]
R340  2K  [0402]
U51  F104S8A  [qfn_vsc8514]  (sections A,B)
sheet 25 QSG PHY2
C464  0.1uF  [0402]
C465  10uF  [0603]
C466  1uF  [0402]
C467  0.1uF  [0402]
C468  0.1uF  [0402]
C469  0.1uF  [0402]
C470  0.1uF  [0402]
C471  0.1uF  [0402]
C472  0.1uF  [0402]
C473  0.1uF  [0402]
C474  0.1uF  [0402]
C475  0.1uF  [0402]
C476  0.1uF  [0402]
C477  10uF  [0603]
C478  1uF  [0402]
C479  0.1uF  [0402]
C480  0.1uF  [0402]
C481  0.1uF  [0402]
C482  10uF  [0603]
C483  10uF  [0603]
C484  1uF  [0402]
C485  0.1uF  [0402]
C486  0.1uF  [0402]
C487  0.1uF  [0402]
C488  0.1uF  [0402]
C489  10uF  [0603]
C490  10uF  [0603]
C491  1uF  [0402]
C492  0.1uF  [0402]
C493  0.1uF  [0402]
C494  0.1uF  [0402]
C495  0.1uF  [0402]
C496  1uF  [0402]
FB24  BLM18PG121SN1  [0603]
FB25  BLM18PG121SN1  [0603]
R341  4.7K  [0402]
R342  0  [0402]
R344  4.7K  [0402]
R345  4.7K  [0402]
R346  4.7K  [0402]
R347  4.7K  [0402]
R348  4.7K  [0402]
R349  619  [0402]
R350  1K  [0402]
R351  2K  [0402]
U52  F104S8A  [qfn_vsc8514]  (sections A,B)
sheet 26 QSG RJ45
C497  0.1uF  [0402]
C498  0.1uF  [0402]
C499  0.1uF  [0402]
C500  0.1uF  [0402]
C501  0.1uF  [0402]
C502  0.1uF  [0402]
C503  0.1uF  [0402]
C504  0.1uF  [0402]
C505  1000pF  [1206]
C506  1000pF  [1206]
C507  470pF  [0402]
C508  470pF  [0402]
C509  470pF  [0402]
C510  470pF  [0402]
C511  0.1uF  [0402]
C512  0.1uF  [0402]
C513  0.1uF  [0402]
C514  0.1uF  [0402]
C515  0.1uF  [0402]
C516  0.1uF  [0402]
C517  0.1uF  [0402]
C518  0.1uF  [0402]
C519  1000pF  [1206]
C520  1000pF  [1206]
C521  470pF  [0402]
C522  470pF  [0402]
C523  470pF  [0402]
C524  470pF  [0402]
C525  0.1uF  [0402]
C526  0.1uF  [0402]
C527  0.1uF  [0402]
C528  0.1uF  [0402]
C529  0.1uF  [0402]
C530  0.1uF  [0402]
C531  0.1uF  [0402]
C532  0.1uF  [0402]
C533  1000pF  [1206]
C534  1000pF  [1206]
C535  470pF  [0402]
C536  470pF  [0402]
C537  470pF  [0402]
C538  470pF  [0402]
C539  0.1uF  [0402]
C540  0.1uF  [0402]
C541  0.1uF  [0402]
C542  0.1uF  [0402]
C543  0.1uF  [0402]
C544  0.1uF  [0402]
C545  0.1uF  [0402]
C546  0.1uF  [0402]
C547  470pF  [0402]
C548  1000pF  [1206]
C549  1000pF  [1206]
C550  470pF  [0402]
C551  1000pF  [1206]
C552  1000pF  [1206]
C553  470pF  [0402]
C554  470pF  [0402]
C555  1000pF  [1206]
C556  0.1uF  [0402]
C557  4.7uF  [0603]
C558  0.01uF  [0402]
C559  1000pF  [1206]
C560  1000pF  [1206]
FB26  BLM18BD601SN1  [0603]
J21  RJ45_LED_8  [con_rj45_2x4_led]  (sections A,B,C,D,E,F,G,H)
R352  75  [0603]
R353  75  [0603]
R354  75  [0603]
R355  75  [0603]
R356  75  [0603]
R357  75  [0603]
R358  75  [0603]
R359  75  [0603]
R360  510  [0402]
R361  510  [0402]
R362  510  [0402]
R363  510  [0402]
R364  75  [0603]
R365  75  [0603]
R366  75  [0603]
R367  75  [0603]
R368  75  [0603]
R369  75  [0603]
R370  75  [0603]
R371  75  [0603]
R372  510  [0402]
R373  510  [0402]
R374  510  [0402]
R375  510  [0402]
R376  75  [0603]
R377  75  [0603]
R378  75  [0603]
R379  75  [0603]
R380  75  [0603]
R381  75  [0603]
R382  75  [0603]
R383  75  [0603]
R384  510  [0402]
R385  510  [0402]
R386  510  [0402]
R387  510  [0402]
R388  75  [0603]
R389  75  [0603]
R390  75  [0603]
R391  75  [0603]
R392  75  [0603]
R393  75  [0603]
R394  75  [0603]
R395  75  [0603]
R396  510  [0402]
R397  510  [0402]
R398  510  [0402]
R399  510  [0402]
T4  H5008  [mag_h5008]
T5  H5008  [mag_h5008]
T6  H5008  [mag_h5008]
T7  H5008  [mag_h5008]
T8  H5008  [mag_h5008]
T9  H5008  [mag_h5008]
T10  H5008  [mag_h5008]
T11  H5008  [mag_h5008]

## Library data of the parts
C368 C370 C371 C373 C397 C399-C401 C558 C1070 C1072-C1074 C1104 C1106-C1108 = CAP: VOLTAGE: 25V
C369 C384-C393 C395 C396 C398 C403 C404 C413-C424 C426-C431 C434-C443 C446-C448 C452-C455 C459-C462 C464 C467-C476 C479-C481 C485-C488 C492-C495 C497-C504 C511-C518 C525-C532 C539-C546 C556 C1071 C1076 C1077 C1086-C1097 C1099-C1103 C1105 C1110 C1111 C1120-C1131 C1133-C1137 = CAP: VOLTAGE: 16V
C372 C375 C381 C411 C1084 C1118 = CAP: BOM_IGNORE: DNP; VOLTAGE: 50V
C374 C376 C382 C402 C405 C408 C505 C506 C519 C520 C533 C534 C548 C549 C551 C552 C555 C559 C560 C1075 C1078 C1081 C1109 C1112 C1115 = CAP: VOLTAGE: 2KV
C377-C380 C406 C407 C409 C410 C507-C510 C521-C524 C535-C538 C547 C550 C553 C554 C1079 C1080 C1082 C1083 C1113 C1114 C1116 C1117 = CAP: VOLTAGE: 50V
C383 C394 C412 C425 C432 C433 C444 C445 C449-C451 C456-C458 C463 C465 C466 C477 C478 C482-C484 C489-C491 C496 C557 C1085 C1098 C1119 C1132 = CAP: VOLTAGE: 6.3V
FB20-FB26 FB44 FB45 = BEAD: Vendor: Murata
J19 = RJ45_LED_2X1: MPN: 10118075-510B010LF; TYPE: CON; Vendor: FCI
L5 = IND_IRON: MPN: SWPA252012S2R2MT; TYPE: IND; Vendor: Sunlord
R277-R286 R288-R290 R292-R295 R297 R299-R321 R323-R325 R329-R331 R334 R336 R337 R339 R341 R342 R344 R345 R347 R348 R350 R352-R399 R724-R741 R745-R763 R767 = RES: TOL: 5%
R296 R326 R333 R335 R346 R742 R764 = RES: BOM_IGNORE: DNP; TOL: 5%
R298 R327 R328 R338 R340 R349 R351 R743 R744 R765 R766 = RES: TOL: 1%
T2 T3 T12 T13 = H5007: TYPE: XFMR; Vendor: Pulse
U45 = RTL8211E-VB: MPN: RTL8211E-VL-CG; TYPE: IC; Vendor: Realtek
Y3 Y4 Y9 Y10 = CRYSTAL_4PIN_v2: MPN: 3.2x2.5mm,+/-20ppm; TYPE: XTAL
J20 J40 J41 = RJ45_LED: MPN: 133745; TYPE: CON; Vendor: ERNI
L6 L17 L18 = IND_IRON: MPN: SWPA252012S4R7MT; TYPE: IND; Vendor: Sunlord
U48 U82 U83 = RTL8211DN: MPN: RTL8211DN-VB-GR; TYPE: IC; Vendor: Realtek
U51 = VSC8514: ID: 1; TYPE: IC; Vendor: Freescale
U52 = VSC8514: ID: 2; TYPE: IC; Vendor: Freescale
J21 = RJ45_LED_8: MPN: 10118077-510B010LF; TYPE: CON; Vendor: FCI
T4-T11 = GST5009LF: TYPE: XFMR; Vendor: Pulse

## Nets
1V0: C449.1 C450.1 C451.1 C452.1 C453.1 C454.1 C455.1 C482.1 C483.1 C484.1 C485.1 C486.1 C487.1 C488.1 FB22.1 FB24.1 U51.E5(VDD1) U51.E7(VDD1) U51.E10(VDD1) U51.E13(VDD1) U51.E15(VDD1) U51.E17(VDD1) U51.E19(VDD1) U51.E21(VDD1) U51.E23(VDD1) U51.E25(VDD1) U52.E5(VDD1) U52.E7(VDD1) U52.E10(VDD1) U52.E13(VDD1) U52.E15(VDD1) U52.E17(VDD1) U52.E19(VDD1) U52.E21(VDD1) U52.E23(VDD1) U52.E25(VDD1) ; also on sheet 33
1V0A_QSG1: C432.1 C433.1 C435.1 C436.1 C437.1 C438.1 C439.1 C440.1 C441.1 FB22.2 U51.E1(VDD1A) U51.E11(VDD1A) U51.E14(VDD1A) U51.E16(VDD1A) U51.E28(VDD1A) U51.E30(VDD1A) U51.E32(VDD1A) U51.E34(VDD1A) U51.E36(VDD1A)
1V0A_QSG2: C465.1 C466.1 C467.1 C468.1 C469.1 C471.1 C472.1 C473.1 C474.1 FB24.2 U52.E1(VDD1A) U52.E11(VDD1A) U52.E14(VDD1A) U52.E16(VDD1A) U52.E28(VDD1A) U52.E30(VDD1A) U52.E32(VDD1A) U52.E34(VDD1A) U52.E36(VDD1A)
1V05_EC2_AVDD: C383.1 C384.1 C391.1 C392.1 C393.1 L5.2 R297.2 U45.3(AVDD10) U45.9(AVDD10) U45.40(AVDD10)
1V05_EC2_DVDD: C387.1 C388.1 R297.1 U45.28(DVDD10) U45.36(DVDD10)
1V05_SG1_AVDD: C1085.1 C1086.1 C1092.1 C1093.1 C1094.1 C1095.1 C1096.1 C1097.1 L17.2 R745.2 U82.3(AVDD10) U82.9(AVDD10) U82.12(AVDD10) U82.16(AVDD10) U82.23(AVDD10) U82.24(REGV15) U82.79(AVDD10)
1V05_SG1_DVDD: C1087.1 C1088.1 R745.1 U82.47(DVDD10) U82.66(DVDD10)
1V05_SG2_AVDD: C1119.1 C1120.1 C1126.1 C1127.1 C1128.1 C1129.1 C1130.1 C1131.1 L18.2 R767.2 U83.3(AVDD10) U83.9(AVDD10) U83.12(AVDD10) U83.16(AVDD10) U83.23(AVDD10) U83.24(REGV15) U83.79(AVDD10)
1V05_SG2_DVDD: C1121.1 C1122.1 R767.1 U83.47(DVDD10) U83.66(DVDD10)
1V05_SG_AVDD: C412.1 C413.1 C419.1 C420.1 C421.1 C422.1 C423.1 C424.1 L6.2 R329.2 U48.3(AVDD10) U48.9(AVDD10) U48.12(AVDD10) U48.16(AVDD10) U48.23(AVDD10) U48.24(REGV15) U48.79(AVDD10)
1V05_SG_DVDD: C414.1 C415.1 R329.1 U48.47(DVDD10) U48.66(DVDD10)
2V5: C385.1 C386.1 C429.1 C430.1 C456.1 C457.1 C458.1 C459.1 C460.1 C461.1 C462.1 C489.1 C490.1 C491.1 C492.1 C493.1 C494.1 C495.1 C556.1 C1102.1 C1103.1 C1136.1 C1137.1 FB23.2 FB25.2 FB26.1 R300.2 R301.2 R302.2 R303.2 R311.1 R312.1 R314.1 R330.2 R333.2 R334.2 R335.2 R336.1 R341.2 R344.2 R345.2 R346.2 R347.1 R728.1 R729.1 R731.1 R750.1 R751.1 R753.1 U45.15(DVDD33) U45.21(DVDD33) U48.34(DVDD33) U48.40(DVDD33) U51.E3(VDD25) U51.E4(VDD25) U51.E6(VDD25) U51.E8(VDD25) U51.E9(VDDMDIO) U51.E12(VDD25) U51.E18(VDD25) U51.E20(VDD25) U51.E22(VDD25) U51.E24(VDD25) U51.E26(VDD25) U52.E3(VDD25) U52.E4(VDD25) U52.E6(VDD25) U52.E8(VDD25) U52.E9(VDDMDIO) U52.E12(VDD25) U52.E18(VDD25) U52.E20(VDD25) U52.E22(VDD25) U52.E24(VDD25) U52.E26(VDD25) U82.34(DVDD33) U82.40(DVDD33) U83.34(DVDD33) U83.40(DVDD33) ; also on sheet 8 12 35
2V5_LED: C557.1 C558.1 FB26.2 J21.A9 J21.A11 J21.B9 J21.B11 J21.C9 J21.C11 J21.D9 J21.D11 J21.E9 J21.E11 J21.F9 J21.F11 J21.G9 J21.G11 J21.H9(G9) J21.H11(G11)
2V5A_QSG1: C444.1 C445.1 C446.1 C447.1 C448.1 FB23.1 U51.E27(VDD25A) U51.E29(VDD25A) U51.E31(VDD25A) U51.E33(VDD25A) U51.E35(VDD25A) U51.E37(VDD25A)
2V5A_QSG2: C477.1 C478.1 C479.1 C480.1 C481.1 FB25.1 U52.E27(VDD25A) U52.E29(VDD25A) U52.E31(VDD25A) U52.E33(VDD25A) U52.E35(VDD25A) U52.E37(VDD25A)
3V3: C389.1 C390.1 C394.1 C395.1 C396.1 C416.1 C417.1 C418.1 C425.1 C426.1 C427.1 C428.1 C1089.1 C1090.1 C1091.1 C1098.1 C1099.1 C1100.1 C1101.1 C1123.1 C1124.1 C1125.1 C1132.1 C1133.1 C1134.1 C1135.1 FB20.1 FB21.1 FB44.1 FB45.1 R293.1 R295.1 R304.2 R306.2 R318.2 R321.1 R324.1 R325.1 R735.2 R736.1 R740.1 R741.1 R757.2 R758.1 R760.1 R762.1 R763.1 U45.6(AVDD33) U45.37(DVDD33) U45.41(AVDD33) U45.44(VDDREG) U45.45(VDDREG) U48.6(AVDD33) U48.25(AVDD33) U48.51(DVDD33) U48.67(DVDD33) U48.80(AVDD33) U48.84(VDDREG) U48.85(VDDREG) U82.6(AVDD33) U82.25(AVDD33) U82.51(DVDD33) U82.67(DVDD33) U82.80(AVDD33) U82.84(VDDREG) U82.85(VDDREG) U83.6(AVDD33) U83.25(AVDD33) U83.51(DVDD33) U83.67(DVDD33) U83.80(AVDD33) U83.84(VDDREG) U83.85(VDDREG) ; also on sheet 5 6 7 9 11 12 14 15 16 17 18 27 30 35
GND: C368.1 C369.2 C370.1 C371.1 C372.1 C373.1 C375.2 C376.1 C377.2 C378.2 C379.2 C380.2 C381.2 C382.1 C383.2 C384.2 C385.2 C386.2 C387.2 C388.2 C389.2 C390.2 C391.2 C392.2 C393.2 C394.2 C395.2 C396.2 C397.1 C398.2 C399.1 C400.1 C401.1 C405.1 C406.2 C407.2 C408.1 C409.2 C410.2 C411.2 C412.2 C413.2 C414.2 C415.2 C416.2 C417.2 C418.2 C419.2 C420.2 C421.2 C422.2 C423.2 C424.2 C425.2 C426.2 C427.2 C428.2 C429.2 C430.2 C432.2 C433.2 C435.2 C436.2 C437.2 C438.2 C439.2 C440.2 C441.2 C444.2 C445.2 C446.2 C447.2 C448.2 C449.2 C450.2 C451.2 C452.2 C453.2 C454.2 C455.2 C456.2 C457.2 C458.2 C459.2 C460.2 C461.2 C462.2 C463.2 C465.2 C466.2 C467.2 C468.2 C469.2 C471.2 C472.2 C473.2 C474.2 C477.2 C478.2 C479.2 C480.2 C481.2 C482.2 C483.2 C484.2 C485.2 C486.2 C487.2 C488.2 C489.2 C490.2 C491.2 C492.2 C493.2 C494.2 C495.2 C496.2 C497.1 C498.1 C499.1 C500.1 C501.1 C502.1 C503.1 C504.1 C507.1 C508.1 C509.1 C510.1 C511.1 C512.1 C513.1 C514.1 C515.1 C516.1 C517.1 C518.1 C521.1 C522.1 C523.1 C524.1 C525.1 C526.1 C527.1 C528.1 C529.1 C530.1 C531.1 C532.1 C535.1 C536.1 C537.1 C538.1 C539.1 C540.1 C541.1 C542.1 C543.1 C544.1 C545.1 C546.1 C547.1 C550.1 C551.1 C552.1 C553.1 C554.1 C555.1 C556.2 C557.2 C558.2 C559.1 C560.1 C1070.1 C1071.2 C1072.1 C1073.1 C1074.1 C1078.1 C1079.2 C1080.2 C1081.1 C1082.2 C1083.2 C1084.2 C1085.2 C1086.2 C1087.2 C1088.2 C1089.2 C1090.2 C1091.2 C1092.2 C1093.2 C1094.2 C1095.2 C1096.2 C1097.2 C1098.2 C1099.2 C1100.2 C1101.2 C1102.2 C1103.2 C1104.1 C1105.2 C1106.1 C1107.1 C1108.1 C1112.1 C1113.2 C1114.2 C1115.1 C1116.2 C1117.2 C1118.2 C1119.2 C1120.2 C1121.2 C1122.2 C1123.2 C1124.2 C1125.2 C1126.2 C1127.2 C1128.2 C1129.2 C1130.2 C1131.2 C1132.2 C1133.2 C1134.2 C1135.2 C1136.2 C1137.2 J19.A12 J20.12 J40.10 R298.1 R299.2 R305.2 R310.1 R315.1 R319.1 R320.2 R327.1 R328.1 R337.1 R339.1 R340.1 R348.1 R350.1 R351.1 R727.1 R732.1 R737.2 R738.1 R743.1 R744.1 R749.1 R754.1 R759.2 R765.1 R766.1 U45.47(GND) U45.49(EPAD) U48.15(AGND) U48.19(AGND) U48.20(AGND) U48.27(AGND) U48.48(GTX_CLK) U48.49(TXEN/TXCTL) U48.50(TXD0) U48.53(TXD1) U48.54(TXD2) U48.55(TXD3) U48.57(TXD4) U48.58(TXD5) U48.59(TXD6) U48.60(TXD7) U48.61(TXER) U48.83(GND) U48.87(GND) U48.89(EPAD) U51.139(VSS_CASE) U51.B7(REFCLK_SEL1) U51.B8(REFCLK_SEL0) U51.D9(VSS/EFUSE) U52.139(VSS_CASE) U52.B7(REFCLK_SEL1) U52.B8(REFCLK_SEL0) U52.D9(VSS/EFUSE) U82.15(AGND) U82.19(AGND) U82.20(AGND) U82.27(AGND) U82.48(GTX_CLK) U82.49(TXEN/TXCTL) U82.50(TXD0) U82.53(TXD1) U82.54(TXD2) U82.55(TXD3) U82.57(TXD4) U82.58(TXD5) U82.59(TXD6) U82.60(TXD7) U82.61(TXER) U82.83(GND) U82.87(GND) U82.89(EPAD) U83.15(AGND) U83.19(AGND) U83.20(AGND) U83.27(AGND) U83.48(GTX_CLK) U83.49(TXEN/TXCTL) U83.50(TXD0) U83.53(TXD1) U83.54(TXD2) U83.55(TXD3) U83.57(TXD4) U83.58(TXD5) U83.59(TXD6) U83.60(TXD7) U83.61(TXER) U83.83(GND) U83.87(GND) U83.89(EPAD) Y3.2 Y3.4 Y4.2 Y4.4 Y9.2 Y9.4 Y10.2 Y10.4 ; also on sheet 3 4 5 6 7 8 9 10 11 12 13 14 15 16 17 18 19 27 28 29 30 31 32 33 34 35 36 37
EARTH: C374.2 C376.2 C382.2 C402.2 C405.2 C408.2 C505.1 C506.1 C519.1 C520.1 C533.1 C534.1 C548.1 C549.1 C551.2 C552.2 C555.2 C559.2 C560.2 C1075.2 C1078.2 C1081.2 C1109.2 C1112.2 C1115.2 J19.25 J19.26 J20.13 J20.14 J21.97 J21.98 J21.99 J21.100 J40.13 J40.14 J41.13 J41.14 ; also on sheet 10 14 16 19 37
EC2_GTXCLK: U45.22(TXC) ; also on sheet 8
EC2_INT_N: R292.2 ; also on sheet 7
EC2_LED0: R289.1 R304.1 U45.34(LED0/PHY_AD0)
EC2_LED1: R290.1 R305.1 U45.35(LED1/PHY_AD1)
EC2_MDI0_N: T2.11 U45.2(MDI-[0])
EC2_MDI0_P: T2.12 U45.1(MDI+[0])
EC2_MDI1_N: T2.8 U45.5(MDI-[1])
EC2_MDI1_P: T2.9 U45.4(MDI+[1])
EC2_MDI2_N: T2.5 U45.8(MDI-[2])
EC2_MDI2_P: T2.6 U45.7(MDI+[2])
EC2_MDI3_N: T2.2 U45.11(MDI-[3])
EC2_MDI3_P: T2.3 U45.10(MDI+[3])
EC2_MDX0_N: J19.A2 T2.14
EC2_MDX0_P: J19.A1 T2.13
EC2_MDX1_N: J19.A6 T2.17
EC2_MDX1_P: J19.A3 T2.16
EC2_MDX2_N: J19.A5 T2.20
EC2_MDX2_P: J19.A4 T2.19
EC2_MDX3_N: J19.A8 T2.23
EC2_MDX3_P: J19.A7 T2.22
EC2_PME_N: R294.2 ; also on sheet 7
EC2_REFCLK: R288.2 ; also on sheet 8
EC2_RST_N: R295.2 U45.29(~{PHYRST}) ; also on sheet 29
EC2_RXCLK: R281.1 ; also on sheet 8
EC2_RXCTL: R286.1 R303.1 ; also on sheet 8
EC2_RXD0: R280.1 R299.1 ; also on sheet 8
EC2_RXD1: R283.1 R300.1 ; also on sheet 8
EC2_RXD2: R284.1 R301.1 ; also on sheet 8
EC2_RXD3: R285.1 R302.1 ; also on sheet 8
EC2_RXDLY: R306.1 U45.32(LED2/RXDLY)
EC2_TXCTL: U45.27(TXCTL) ; also on sheet 8
EC2_TXD0: U45.23(TXD0) ; also on sheet 8
EC2_TXD1: U45.24(TXD1) ; also on sheet 8
EC2_TXD2: U45.25(TXD2) ; also on sheet 8
EC2_TXD3: U45.26(TXD3) ; also on sheet 8
EMI1_MDC: U45.30(MDC) U48.72(MDC) U51.C11(MDC) U52.C11(MDC) U82.72(MDC) U83.72(MDC) ; also on sheet 8
EMI1_MDIO: U45.31(MDIO) U48.73(MDIO) U51.D10(MDIO) U52.D10(MDIO) U82.73(MDIO) U83.73(MDIO) ; also on sheet 8
QSG1_INT_N: R330.1 R331.2 ; also on sheet 29
QSG1_LED0: R361.1 U51.C3(LED0_PHY1)
QSG1_LED1: R363.1 U51.B2(LED1_PHY1)
QSG1_MDI0_N: T5.3 U51.B17(P1_D0N)
QSG1_MDI0_P: T5.2 U51.B18(P1_D0P)
QSG1_MDI1_N: T5.6 U51.C28(P1_D1N)
QSG1_MDI1_P: T5.5 U51.C29(P1_D1P)
QSG1_MDI2_N: T5.9 U51.B15(P1_D2N)
QSG1_MDI2_P: T5.8 U51.B16(P1_D2P)
QSG1_MDI3_N: T5.12 U51.C26(P1_D3N)
QSG1_MDI3_P: T5.11 U51.C27(P1_D3P)
QSG1_MDX0_N: J21.A2 T5.22
QSG1_MDX0_P: J21.A1 T5.23
QSG1_MDX1_N: J21.A6 T5.19
QSG1_MDX1_P: J21.A3 T5.20
QSG1_MDX2_N: J21.A5 T5.16
QSG1_MDX2_P: J21.A4 T5.17
QSG1_MDX3_N: J21.A8 T5.13
QSG1_MDX3_P: J21.A7 T5.14
QSG1_REFCLK_N: C443.1 ; also on sheet 30
QSG1_REFCLK_P: C442.1 ; also on sheet 30
QSG1_RST_N: R336.2 U51.B5(~{RESET}) ; also on sheet 29
QSG2_INT_N: R341.1 R342.2 ; also on sheet 29
QSG2_LED0: R373.1 U51.E2(LED0_PHY0)
QSG2_LED1: R375.1 U51.D1(LED1_PHY0)
QSG2_MDI0_N: T6.3 U51.D30(P0_D0N)
QSG2_MDI0_P: T6.2 U51.D31(P0_D0P)
QSG2_MDI1_N: T6.6 U51.C24(P0_D1N)
QSG2_MDI1_P: T6.5 U51.C25(P0_D1P)
QSG2_MDI2_N: T6.9 U51.C23(P0_D2N)
QSG2_MDI2_P: T6.8 U51.D29(P0_D2P)
QSG2_MDI3_N: T6.12 U51.C21(P0_D3N)
QSG2_MDI3_P: T6.11 U51.C22(P0_D3P)
QSG2_MDX0_N: J21.B2 T6.22
QSG2_MDX0_P: J21.B1 T6.23
QSG2_MDX1_N: J21.B6 T6.19
QSG2_MDX1_P: J21.B3 T6.20
QSG2_MDX2_N: J21.B5 T6.16
QSG2_MDX2_P: J21.B4 T6.17
QSG2_MDX3_N: J21.B8 T6.13
QSG2_MDX3_P: J21.B7 T6.14
QSG2_REFCLK_N: C476.1 ; also on sheet 30
QSG2_REFCLK_P: C475.1 ; also on sheet 30
QSG2_RST_N: R347.2 U52.B5(~{RESET}) ; also on sheet 29
QSG3_LED0: R385.1 U51.B4(LED0_PHY3)
QSG3_LED1: R387.1 U51.C6(LED1_PHY3)
QSG3_MDI0_N: T8.3 U51.C36(P3_D0N)
QSG3_MDI0_P: T8.2 U51.C1(P3_D0P)
QSG3_MDI1_N: T8.6 U51.D34(P3_D1N)
QSG3_MDI1_P: T8.5 U51.D35(P3_D1P)
QSG3_MDI2_N: T8.9 U51.C34(P3_D2N)
QSG3_MDI2_P: T8.8 U51.C35(P3_D2P)
QSG3_MDI3_N: T8.12 U51.D32(P3_D3N)
QSG3_MDI3_P: T8.11 U51.D33(P3_D3P)
QSG3_MDX0_N: J21.C2 T8.22
QSG3_MDX0_P: J21.C1 T8.23
QSG3_MDX1_N: J21.C6 T8.19
QSG3_MDX1_P: J21.C3 T8.20
QSG3_MDX2_N: J21.C5 T8.16
QSG3_MDX2_P: J21.C4 T8.17
QSG3_MDX3_N: J21.C8 T8.13
QSG3_MDX3_P: J21.C7 T8.14
QSG4_LED0: R396.1 U51.C5(LED0_PHY2)
QSG4_LED1: R397.1 U51.D5(LED1_PHY2)
QSG4_MDI0_N: T10.3 U51.C32(P2_D0N)
QSG4_MDI0_P: T10.2 U51.C33(P2_D0P)
QSG4_MDI1_N: T10.6 U51.B19(P2_D1N)
QSG4_MDI1_P: T10.5 U51.B20(P2_D1P)
QSG4_MDI2_N: T10.9 U51.A9(P2_D2N)
QSG4_MDI2_P: T10.8 U51.A10(P2_D2P)
QSG4_MDI3_N: T10.12 U51.C30(P2_D3N)
QSG4_MDI3_P: T10.11 U51.C31(P2_D3P)
QSG4_MDX0_N: J21.D2 T10.22
QSG4_MDX0_P: J21.D1 T10.23
QSG4_MDX1_N: J21.D6 T10.19
QSG4_MDX1_P: J21.D3 T10.20
QSG4_MDX2_N: J21.D5 T10.16
QSG4_MDX2_P: J21.D4 T10.17
QSG4_MDX3_N: J21.D8 T10.13
QSG4_MDX3_P: J21.D7 T10.14
QSG5_LED0: R360.1 U52.C3(LED0_PHY1)
QSG5_LED1: R362.1 U52.B2(LED1_PHY1)
QSG5_MDI0_N: T4.3 U52.B17(P1_D0N)
QSG5_MDI0_P: T4.2 U52.B18(P1_D0P)
QSG5_MDI1_N: T4.6 U52.C28(P1_D1N)
QSG5_MDI1_P: T4.5 U52.C29(P1_D1P)
QSG5_MDI2_N: T4.9 U52.B15(P1_D2N)
QSG5_MDI2_P: T4.8 U52.B16(P1_D2P)
QSG5_MDI3_N: T4.12 U52.C26(P1_D3N)
QSG5_MDI3_P: T4.11 U52.C27(P1_D3P)
QSG5_MDX0_N: J21.E2 T4.22
QSG5_MDX0_P: J21.E1 T4.23
QSG5_MDX1_N: J21.E6 T4.19
QSG5_MDX1_P: J21.E3 T4.20
QSG5_MDX2_N: J21.E5 T4.16
QSG5_MDX2_P: J21.E4 T4.17
QSG5_MDX3_N: J21.E8 T4.13
QSG5_MDX3_P: J21.E7 T4.14
QSG6_LED0: R372.1 U52.E2(LED0_PHY0)
QSG6_LED1: R374.1 U52.D1(LED1_PHY0)
QSG6_MDI0_N: T7.3 U52.D30(P0_D0N)
QSG6_MDI0_P: T7.2 U52.D31(P0_D0P)
QSG6_MDI1_N: T7.6 U52.C24(P0_D1N)
QSG6_MDI1_P: T7.5 U52.C25(P0_D1P)
QSG6_MDI2_N: T7.9 U52.C23(P0_D2N)
QSG6_MDI2_P: T7.8 U52.D29(P0_D2P)
QSG6_MDI3_N: T7.12 U52.C21(P0_D3N)
QSG6_MDI3_P: T7.11 U52.C22(P0_D3P)
QSG6_MDX0_N: J21.F2 T7.22
QSG6_MDX0_P: J21.F1 T7.23
QSG6_MDX1_N: J21.F6 T7.19
QSG6_MDX1_P: J21.F3 T7.20
QSG6_MDX2_N: J21.F5 T7.16
QSG6_MDX2_P: J21.F4 T7.17
QSG6_MDX3_N: J21.F8 T7.13
QSG6_MDX3_P: J21.F7 T7.14
QSG7_LED0: R384.1 U52.B4(LED0_PHY3)
QSG7_LED1: R386.1 U52.C6(LED1_PHY3)
QSG7_MDI0_N: T9.3 U52.C36(P3_D0N)
QSG7_MDI0_P: T9.2 U52.C1(P3_D0P)
QSG7_MDI1_N: T9.6 U52.D34(P3_D1N)
QSG7_MDI1_P: T9.5 U52.D35(P3_D1P)
QSG7_MDI2_N: T9.9 U52.C34(P3_D2N)
QSG7_MDI2_P: T9.8 U52.C35(P3_D2P)
QSG7_MDI3_N: T9.12 U52.D32(P3_D3N)
QSG7_MDI3_P: T9.11 U52.D33(P3_D3P)
QSG7_MDX0_N: J21.G2 T9.22
QSG7_MDX0_P: J21.G1 T9.23
QSG7_MDX1_N: J21.G6 T9.19
QSG7_MDX1_P: J21.G3 T9.20
QSG7_MDX2_N: J21.G5 T9.16
QSG7_MDX2_P: J21.G4 T9.17
QSG7_MDX3_N: J21.G8 T9.13
QSG7_MDX3_P: J21.G7 T9.14
QSG8_LED0: R398.1 U52.C5(LED0_PHY2)
QSG8_LED1: R399.1 U52.D5(LED1_PHY2)
QSG8_MDI0_N: T11.3 U52.C32(P2_D0N)
QSG8_MDI0_P: T11.2 U52.C33(P2_D0P)
QSG8_MDI1_N: T11.6 U52.B19(P2_D1N)
QSG8_MDI1_P: T11.5 U52.B20(P2_D1P)
QSG8_MDI2_N: T11.9 U52.A9(P2_D2N)
QSG8_MDI2_P: T11.8 U52.A10(P2_D2P)
QSG8_MDI3_N: T11.12 U52.C30(P2_D3N)
QSG8_MDI3_P: T11.11 U52.C31(P2_D3P)
QSG8_MDX0_N: J21.H2(G2) T11.22
QSG8_MDX0_P: J21.H1(G1) T11.23
QSG8_MDX1_N: J21.H6(G6) T11.19
QSG8_MDX1_P: J21.H3(G3) T11.20
QSG8_MDX2_N: J21.H5(G5) T11.16
QSG8_MDX2_P: J21.H4(G4) T11.17
QSG8_MDX3_N: J21.H8(G8) T11.13
QSG8_MDX3_P: J21.H7(G7) T11.14
QSGMII1_RX_N: U51.D13(QSGMII0_RXN) ; also on sheet 9
QSGMII1_RX_P: U51.D14(QSGMII0_RXP) ; also on sheet 9
QSGMII1_TX_N: C434.1 ; also on sheet 9
QSGMII1_TX_P: C431.1 ; also on sheet 9
QSGMII2_RX_N: U52.D13(QSGMII0_RXN) ; also on sheet 9
QSGMII2_RX_P: U52.D14(QSGMII0_RXP) ; also on sheet 9
QSGMII2_TX_N: C470.1 ; also on sheet 9
QSGMII2_TX_P: C464.1 ; also on sheet 9
SG1_INT_N: R739.2 ; also on sheet 29
SG1_LED0: R733.1 R738.2 U82.68(LED0/PHY_AD0)
SG1_LED1: R734.1 R736.2 U82.69(LED1/PHY_AD1)
SG1_MDI0_N: T12.11 U82.2(MDIN0)
SG1_MDI0_P: T12.12 U82.1(MDIP0)
SG1_MDI1_N: T12.8 U82.5(MDIN1)
SG1_MDI1_P: T12.9 U82.4(MDIP1)
SG1_MDI2_N: T12.5 U82.8(MDIN2)
SG1_MDI2_P: T12.6 U82.7(MDIP2)
SG1_MDI3_N: T12.2 U82.11(MDIN3)
SG1_MDI3_P: T12.3 U82.10(MDIP3)
SG1_MDX0_N: J40.2 T12.14
SG1_MDX0_P: J40.1 T12.13
SG1_MDX1_N: J40.6 T12.17
SG1_MDX1_P: J40.3 T12.16
SG1_MDX2_N: J40.5 T12.20
SG1_MDX2_P: J40.4 T12.19
SG1_MDX3_N: J40.8 T12.23
SG1_MDX3_P: J40.7 T12.22
SG1_RST_N: R740.2 U82.52(~{PHYRST}) ; also on sheet 29
SG2_INT_N: R761.2 ; also on sheet 29
SG2_LED0: R755.1 R760.2 U83.68(LED0/PHY_AD0)
SG2_LED1: R756.1 R758.2 U83.69(LED1/PHY_AD1)
SG2_MDI0_N: T13.11 U83.2(MDIN0)
SG2_MDI0_P: T13.12 U83.1(MDIP0)
SG2_MDI1_N: T13.8 U83.5(MDIN1)
SG2_MDI1_P: T13.9 U83.4(MDIP1)
SG2_MDI2_N: T13.5 U83.8(MDIN2)
SG2_MDI2_P: T13.6 U83.7(MDIP2)
SG2_MDI3_N: T13.2 U83.11(MDIN3)
SG2_MDI3_P: T13.3 U83.10(MDIP3)
SG2_MDX0_N: J41.2 T13.14
SG2_MDX0_P: J41.1 T13.13
SG2_MDX1_N: J41.6 T13.17
SG2_MDX1_P: J41.3 T13.16
SG2_MDX2_N: J41.5 T13.20
SG2_MDX2_P: J41.4 T13.19
SG2_MDX3_N: J41.8 T13.23
SG2_MDX3_P: J41.7 T13.22
SG2_RST_N: R763.2 U83.52(~{PHYRST}) ; also on sheet 29
SG_INT_N: R323.2 ; also on sheet 7
SG_LED0: R316.1 R321.2 U48.68(LED0/PHY_AD0)
SG_LED1: R317.1 R319.2 U48.69(LED1/PHY_AD1)
SG_MDI0_N: T3.11 U48.2(MDIN0)
SG_MDI0_P: T3.12 U48.1(MDIP0)
SG_MDI1_N: T3.8 U48.5(MDIN1)
SG_MDI1_P: T3.9 U48.4(MDIP1)
SG_MDI2_N: T3.5 U48.8(MDIN2)
SG_MDI2_P: T3.6 U48.7(MDIP2)
SG_MDI3_N: T3.2 U48.11(MDIN3)
SG_MDI3_P: T3.3 U48.10(MDIP3)
SG_MDX0_N: J20.2 T3.14
SG_MDX0_P: J20.1 T3.13
SG_MDX1_N: J20.6 T3.17
SG_MDX1_P: J20.3 T3.16
SG_MDX2_N: J20.5 T3.20
SG_MDX2_P: J20.4 T3.19
SG_MDX3_N: J20.8 T3.23
SG_MDX3_P: J20.7 T3.22
SG_RST_N: R325.2 U48.52(~{PHYRST}) ; also on sheet 29
SGMII1_RX_N: U82.18(HSON) ; also on sheet 9
SGMII1_RX_P: U82.17(HSOP) ; also on sheet 9
SGMII1_TX_N: C1077.2 ; also on sheet 9
SGMII1_TX_P: C1076.2 ; also on sheet 9
SGMII2_RX_N: U83.18(HSON) ; also on sheet 9
SGMII2_RX_P: U83.17(HSOP) ; also on sheet 9
SGMII2_TX_N: C1111.2 ; also on sheet 9
SGMII2_TX_P: C1110.2 ; also on sheet 9
SGMII_RX_N: U48.18(HSON) ; also on sheet 8
SGMII_RX_P: U48.17(HSOP) ; also on sheet 8
SGMII_TX_N: C404.2 ; also on sheet 8
SGMII_TX_P: C403.2 ; also on sheet 8
N16891950: R307.1 T3.15
N16891952: C402.1 R307.2 R308.2 R309.2 R313.2
N16891962: R308.1 T3.18
N16891966: R309.1 T3.21
N16891978: R313.1 T3.24
N16892036: C397.2 C399.2 C400.2 C401.2 T3.1 T3.4 T3.7 T3.10
N16892171: C398.1 FB21.2 J20.9
N16892215: C407.1 J20.10 R316.2
N16892219: C406.1 J20.11 R317.2
N16892768: R311.2 U48.43(RXD7/AN0)
N16892846: R312.2 U48.44(RXER/AN1)
N16894213: R314.2 U48.46(CRS/MII1)
N16894217: R315.2 U48.45(COL/MII0)
N16894418: R323.1 U48.75(~{INT})
N16899326: C403.1 U48.13(HSIP)
N16899338: C404.1 U48.14(HSIN)
N16900249: R318.1 U48.70(LED2/MDI0)
N16900569: R320.1 U48.71(LED3/MDI1)
N16900702: C409.1 U48.81(CKXTAL1) Y4.1
N16900720: C410.1 U48.82(CKXTAL2) Y4.3
N16902304: R324.2 U48.77(ENSWREG)
N16902556: R328.2 U48.26(REXT)
N16903120: R327.2 U48.78(RSET)
N16909680: L6.1 R326.1 U48.88(REG_OUT)
N16909742: C411.1 R326.2
N16927443: R310.2 U48.39(RXD4/SELRGV)
N16974225: R277.1 T2.15
N16974227: C374.1 R277.2 R278.2 R279.2 R282.2
N16974244: R278.1 T2.18
N16974248: R279.1 T2.21
N16974260: R282.1 T2.24
N16974504: C369.1 FB20.2 J19.A9
N16974534: C378.1 J19.A10 R289.2
N16974536: C377.1 J19.A11 R290.2
N17582904: R353.1 T5.24
N17582906: C506.2 R353.2 R355.2 R357.2 R359.2
N17582916: R355.1 T5.21
N17582920: R357.1 T5.18
N17582932: R359.1 T5.15
N17584782: C498.2 T5.1
N17584786: C500.2 T5.4
N17584789: C502.2 T5.7
N17584792: C504.2 T5.10
N17584836: C512.2 T6.1
N17584840: C514.2 T6.4
N17584844: C516.2 T6.7
N17584847: C518.2 T6.10
N17584869: R331.1 U51.C10(MDINT)
N17584889: C528.2 T8.4
N17584893: C526.2 T8.1
N17584896: C530.2 T8.7
N17584902: C532.2 T8.10
N17584942: C542.2 T10.4
N17584944: C541.2 T10.1
N17584949: C544.2 T10.7
N17584952: C546.2 T10.10
N17584987: C508.2 J21.A12 R363.2
N17584990: C510.2 J21.A10 R361.2
N17585015: C522.2 J21.B12 R375.2
N17585018: C524.2 J21.B10 R373.2
N17585035: C536.2 J21.C12 R387.2
N17585038: C538.2 J21.C10 R385.2
N17585055: C547.2 J21.D12 R397.2
N17585058: C550.2 J21.D10 R396.2
N17585063: C553.2 J21.H12(G12) R399.2
N17585067: C554.2 J21.H10(G10) R398.2
N17585093: C497.2 T4.1
N17585097: C499.2 T4.4
N17585100: C501.2 T4.7
N17585103: C503.2 T4.10
N17585145: C511.2 T7.1
N17585149: C513.2 T7.4
N17585152: C515.2 T7.7
N17585155: C517.2 T7.10
N17585198: C527.2 T9.4
N17585202: C525.2 T9.1
N17585205: C529.2 T9.7
N17585209: C531.2 T9.10
N17585248: C540.2 T11.4
N17585251: C539.2 T11.1
N17585256: C543.2 T11.7
N17585259: C545.2 T11.10
N17585292: C507.2 J21.E12 R362.2
N17585295: C509.2 J21.E10 R360.2
N17585312: C521.2 J21.F12 R374.2
N17585315: C523.2 J21.F10 R372.2
N17585332: C535.2 J21.G12 R386.2
N17585335: C537.2 J21.G10 R384.2
N17590523: L5.1 R296.1 U45.48(REG_OUT)
N17590546: C381.1 R296.2
N17590598: C372.2 R281.2 U45.19(RXC)
N17590603: R280.2 U45.14(RXD0/SELRGV)
N17590606: R283.2 U45.16(RXD1/TXDLY)
N17590608: R284.2 U45.17(RXD2/AN0)
N17590610: R285.2 U45.18(RXD3/AN1)
N17590611: R286.2 U45.13(RXCTL/PHY_AD2)
N17590657: C368.2 C370.2 C371.2 C373.2 T2.1 T2.4 T2.7 T2.10
N17590707: R292.1 U45.20(~{INT})
N17590732: C379.1 U45.42(CKXTAL1) Y3.1
N17590735: C380.1 U45.43(CKXTAL2) Y3.3
N17590767: C375.1 R288.1 U45.46(CLK125)
N17590774: R294.1 U45.33(~{PME})
N17590779: R298.2 U45.39(RSET)
N17604579: R339.2 U51.C7(~{JTAG_TRST})
N17629033: R334.1 U51.B12(PHYADD3)
N17629034: R335.1 U51.D26(PHYADD4)
N17629035: R333.1 U51.C19(PHYADD2)
N17629454: R337.2 U51.D8(COMA_MODE)
N17629729: C463.1 U51.A7(REF_FILT)
N17629871: R340.2 U51.A8(REF_REXT)
N17632317: R365.1 T6.24
N17632319: C520.2 R365.2 R367.2 R369.2 R371.2
N17632321: R367.1 T6.21
N17632325: R369.1 T6.18
N17632337: R371.1 T6.15
N17632726: C534.2 R377.2 R379.2 R381.2 R383.2
N17632728: R377.1 T8.24
N17632740: R381.1 T8.18
N17632744: R379.1 T8.21
N17632760: R383.1 T8.15
N17633242: R390.1 T10.24
N17633244: C549.2 R390.2 R391.2 R393.2 R395.2
N17633254: R391.1 T10.21
N17633258: R393.1 T10.18
N17633270: R395.1 T10.15
N17639917: C496.1 U52.A7(REF_FILT)
N17639934: R351.2 U52.A8(REF_REXT)
N17639958: R349.2 U52.D18(SEDES_REXT_1)
N17639964: R349.1 U52.D17(SEDES_REXT_0)
N17639984: R350.2 U52.C7(~{JTAG_TRST})
N17640717: R342.1 U52.C10(MDINT)
N17650951: R345.1 U52.B12(PHYADD3)
N17650952: R346.1 U52.D26(PHYADD4)
N17650953: R344.1 U52.C19(PHYADD2)
N17650962: R348.2 U52.D8(COMA_MODE)
N17792541: C505.2 R352.2 R354.2 R356.2 R358.2
N17792543: C519.2 R364.2 R366.2 R368.2 R370.2
N17792545: C533.2 R376.2 R378.2 R380.2 R382.2
N17792547: C548.2 R388.2 R389.2 R392.2 R394.2
N17792549: R352.1 T4.24
N17792551: R354.1 T4.21
N17792553: R356.1 T4.18
N17792555: R358.1 T4.15
N17792589: R364.1 T7.24
N17792591: R366.1 T7.21
N17792593: R368.1 T7.18
N17792595: R370.1 T7.15
N17792630: R378.1 T9.21
N17792632: R376.1 T9.24
N17792634: R382.1 T9.15
N17792636: R380.1 T9.18
N17792669: R388.1 T11.24
N17792671: R389.1 T11.21
N17792673: R392.1 T11.18
N17792675: R394.1 T11.15
N17823659: C443.2 U51.D12(REFCLK_N)
N17823662: C442.2 U51.D11(REFCLK_P)
N17824163: C476.2 U52.D12(REFCLK_N)
N17824166: C475.2 U52.D11(REFCLK_P)
N18200115: R724.1 T12.15
N18200130: R726.1 T12.21
N18200132: C1075.1 R724.2 R725.2 R726.2 R730.2
N18200134: R725.1 T12.18
N18200140: R730.1 T12.24
N18200177: C1070.2 C1072.2 C1073.2 C1074.2 T12.1 T12.4 T12.7 T12.10
N18200226: C1071.1 FB44.2 J40.11
N18200230: C1079.1 J40.12 R734.2
N18200232: C1080.1 J40.9 R733.2
N18200292: R728.2 U82.43(RXD7/AN0)
N18200294: R729.2 U82.44(RXER/AN1)
N18200344: R732.2 U82.45(COL/MII0)
N18200346: R731.2 U82.46(CRS/MII1)
N18200354: R739.1 U82.75(~{INT})
N18200448: L17.1 R742.1 U82.88(REG_OUT)
N18200458: C1084.1 R742.2
N18200620: C1076.1 U82.13(HSIP)
N18200622: C1077.1 U82.14(HSIN)
N18200686: R735.1 U82.70(LED2/MDI0)
N18200704: R737.1 U82.71(LED3/MDI1)
N18200722: C1082.1 U82.81(CKXTAL1) Y9.1
N18200732: C1083.1 U82.82(CKXTAL2) Y9.3
N18200786: R727.2 U82.39(RXD4/SELRGV)
N18200821: R741.2 U82.77(ENSWREG)
N18200841: R744.2 U82.26(REXT)
N18201157: R743.2 U82.78(RSET)
N18205066: R746.1 T13.15
N18205081: R748.1 T13.21
N18205083: C1109.1 R746.2 R747.2 R748.2 R752.2
N18205085: R747.1 T13.18
N18205091: R752.1 T13.24
N18205128: C1104.2 C1106.2 C1107.2 C1108.2 T13.1 T13.4 T13.7 T13.10
N18205177: C1105.1 FB45.2 J41.9 J41.11
N18205181: C1113.1 J41.12 R756.2
N18205183: C1114.1 J41.10 R755.2
N18205243: R750.2 U83.43(RXD7/AN0)
N18205245: R751.2 U83.44(RXER/AN1)
N18205295: R754.2 U83.45(COL/MII0)
N18205297: R753.2 U83.46(CRS/MII1)
N18205305: R761.1 U83.75(~{INT})
N18205399: L18.1 R764.1 U83.88(REG_OUT)
N18205409: C1118.1 R764.2
N18205571: C1110.1 U83.13(HSIP)
N18205573: C1111.1 U83.14(HSIN)
N18205637: R757.1 U83.70(LED2/MDI0)
N18205655: R759.1 U83.71(LED3/MDI1)
N18205673: C1116.1 U83.81(CKXTAL1) Y10.1
N18205683: C1117.1 U83.82(CKXTAL2) Y10.3
N18205737: R749.2 U83.39(RXD4/SELRGV)
N18205772: R762.2 U83.77(ENSWREG)
N18205792: R766.2 U83.26(REXT)
N18206108: R765.2 U83.78(RSET)
N18552106: R293.2 U45.38(ENSWREG)
N18629376: C434.2 U51.D15(QSGMII0_TXN)
N18629379: C431.2 U51.D16(QSGMII0_TXP)
N18629428: C470.2 U52.D15(QSGMII0_TXN)
N18629431: C464.2 U52.D16(QSGMII0_TXP)
N19675149: R338.2 U51.D18(SEDES_REXT_1)
N19675151: R338.1 U51.D17(SEDES_REXT_0)

Not connected (* = marked no-connect by the designer): U45 12(NC)*; U48 21(HSON_CK)* 22(HSOP_CK)* 28(NC1)* 29(NC2)* 30(NC3)* 31(NC4)* 32(RXDV/RXCTL)* 33(RXD0)* 35(RXD1)* 36(RXD2)* 37(RXD3)* 38(RXC)* 41(RXD5/TXDLY)* 42(RXD6/RXDLY)* 56(TXCLK)* 62(TMS)* 63(TCK)* 64(TDO)* 65(TDI)* 74(~{PME})* 76(NC5)* 86(CLK125)*; U51 A1(NC1)* A2(LED2_PHY3)* A3(JTAG_TMS)* A4(NC2)* A5(NC3)* A6(NC4)* B1(THERMDA)* B3(LED2_PHY2)* B6(JTAG_CLK)* B9(GPIO4)* B10(GPIO7)* B11(GPIO13)* B13(RCVRD_CLK0)* B14(TANA_1/NC)* C2(LED3_PHY0)* C4(LED2_PHY1)* C8(JTAG_DO)* C9(JTAG_DI)* C12(HSTST_P/NC)* C13(HSTST_N/NC)* C14(GPIO1)* C15(GPIO3)* C16(GPIO5)* C17(GPIO8)* C18(GPIO12)* C20(RCVRD_CLK1)* D2(LED2_PHY0)* D3(THERMDC_VSS)* D4(LED3_PHY1)* D6(LED3_PHY2)* D7(LED3_PHY3)* D19(GPIO0)* D20(GPIO2)* D21(GPIO6)* D22(GPIO9)* D23(GPIO11)* D24(GPIO10)* D25(GPIO14)* D27(CLK_SQUELCH_IN)* D28(TANA_0/NC)*; U52 A1(NC1)* A2(LED2_PHY3)* A3(JTAG_TMS)* A4(NC2)* A5(NC3)* A6(NC4)* B1(THERMDA)* B3(LED2_PHY2)* B6(JTAG_CLK)* B9(GPIO4)* B10(GPIO7)* B11(GPIO13)* B13(RCVRD_CLK0)* B14(TANA_1/NC)* C2(LED3_PHY0)* C4(LED2_PHY1)* C8(JTAG_DO)* C9(JTAG_DI)* C12(HSTST_P/NC)* C13(HSTST_N/NC)* C14(GPIO1)* C15(GPIO3)* C16(GPIO5)* C17(GPIO8)* C18(GPIO12)* C20(RCVRD_CLK1)* D2(LED2_PHY0)* D3(THERMDC_VSS)* D4(LED3_PHY1)* D6(LED3_PHY2)* D7(LED3_PHY3)* D19(GPIO0)* D20(GPIO2)* D21(GPIO6)* D22(GPIO9)* D23(GPIO11)* D24(GPIO10)* D25(GPIO14)* D27(CLK_SQUELCH_IN)* D28(TANA_0/NC)*; U82 21(HSON_CK)* 22(HSOP_CK)* 28(NC1)* 29(NC2)* 30(NC3)* 31(NC4)* 32(RXDV/RXCTL)* 33(RXD0)* 35(RXD1)* 36(RXD2)* 37(RXD3)* 38(RXC)* 41(RXD5/TXDLY)* 42(RXD6/RXDLY)* 56(TXCLK)* 62(TMS)* 63(TCK)* 64(TDO)* 65(TDI)* 74(~{PME})* 76(NC5)* 86(CLK125)*; U83 21(HSON_CK)* 22(HSOP_CK)* 28(NC1)* 29(NC2)* 30(NC3)* 31(NC4)* 32(RXDV/RXCTL)* 33(RXD0)* 35(RXD1)* 36(RXD2)* 37(RXD3)* 38(RXC)* 41(RXD5/TXDLY)* 42(RXD6/RXDLY)* 56(TXCLK)* 62(TMS)* 63(TCK)* 64(TDO)* 65(TDI)* 74(~{PME})* 76(NC5)* 86(CLK125)*

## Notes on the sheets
sheet 20
- RGMII ETHERNET PORT 2
- 100 ohms
  DIFF PAIRs
- RGMII PHY POWER-ON STRAPPINGs
- SELRGV
- TXDLY
- 2.5V
- AN0
- NWay, advertize all capability
- AN1
- PHY_AD2
- PHY_AD0
- PHY ADDR = 0x05
- PHY_AD1
- RXDLY
sheet 21
- SGMII ETHERNET PORT
- 100 ohms DIFF PAIR
- 100 ohms
  DIFF PAIRs
- 2.5V GMII/RGMII
- NWay, advertize all capability
- SGMII to Coper
- 100 ohms DIFF PAIR
- PHY ADDR = 0x01
- SGMII to Coper
sheet 22
- SGMII ETHERNET PORT 1
- 100 ohms DIFF PAIR
- 100 ohms
  DIFF PAIRs
- 2.5V GMII/RGMII
- NWay, advertize all capability
- SGMII to Coper
- 100 ohms DIFF PAIR
- PHY ADDR = 0x02
- SGMII to Coper
sheet 23
- SGMII ETHERNET PORT 2
- 100 ohms DIFF PAIR
- 100 ohms
  DIFF PAIRs
- 2.5V GMII/RGMII
- NWay, advertize all capability
- SGMII to Coper
- 100 ohms DIFF PAIR
- PHY ADDR = 0x03
- SGMII to Coper
sheet 24
- QSGMII PHY 1
- REFCLK_SEL[1:0] = 00 for 125MHz clock
- PHY ADDR = 0x08~0B
- Join as single point then to analog ground plane
sheet 25
- QSGMII PHY 2
- REFCLK_SEL[1:0] = 00 for 125MHz clock
- PHY ADDR = 0x0C~0F
- Join as single point then to analog ground plane
sheet 26
- QSGMII ETHERNET PORTs
